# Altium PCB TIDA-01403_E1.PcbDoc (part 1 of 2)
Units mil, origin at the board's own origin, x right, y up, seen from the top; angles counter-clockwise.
Board outline 4150 x 3450 mil, 4 copper layers (Top Layer, GND, PWR, Bottom Layer), stack 61.6 mil thick; 155 components, 99 nets, 498 pads, 229 vias.
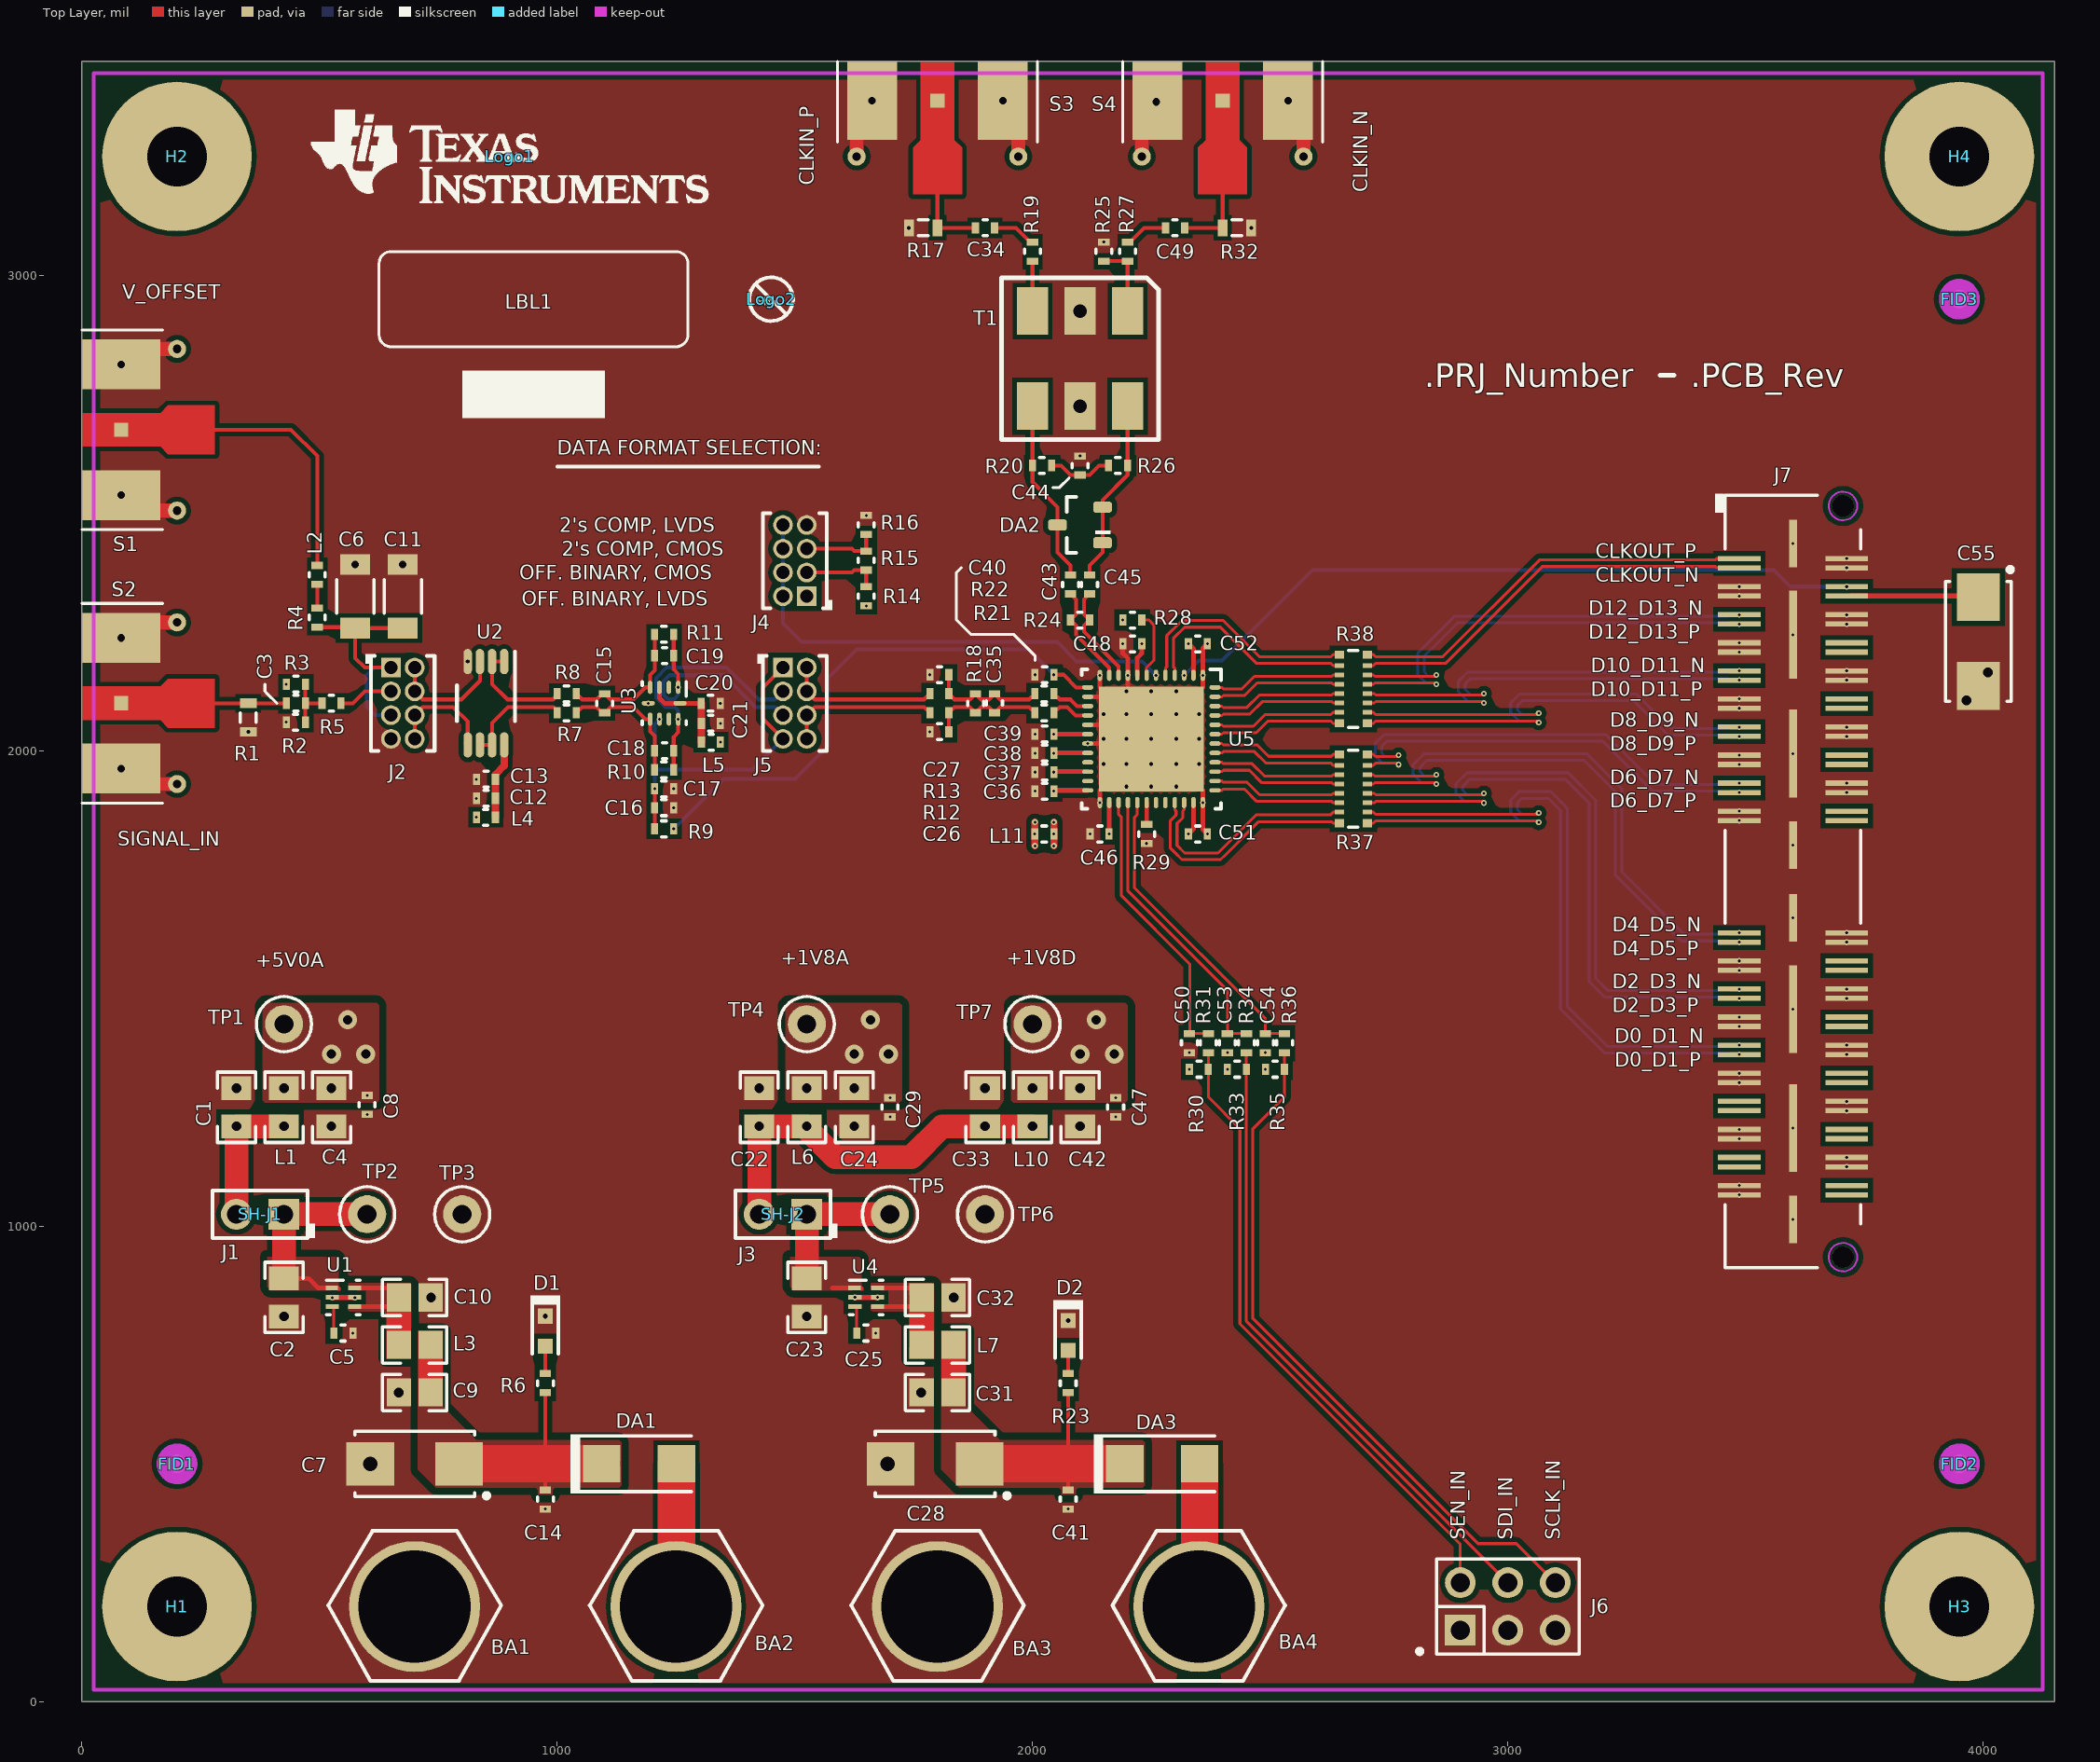
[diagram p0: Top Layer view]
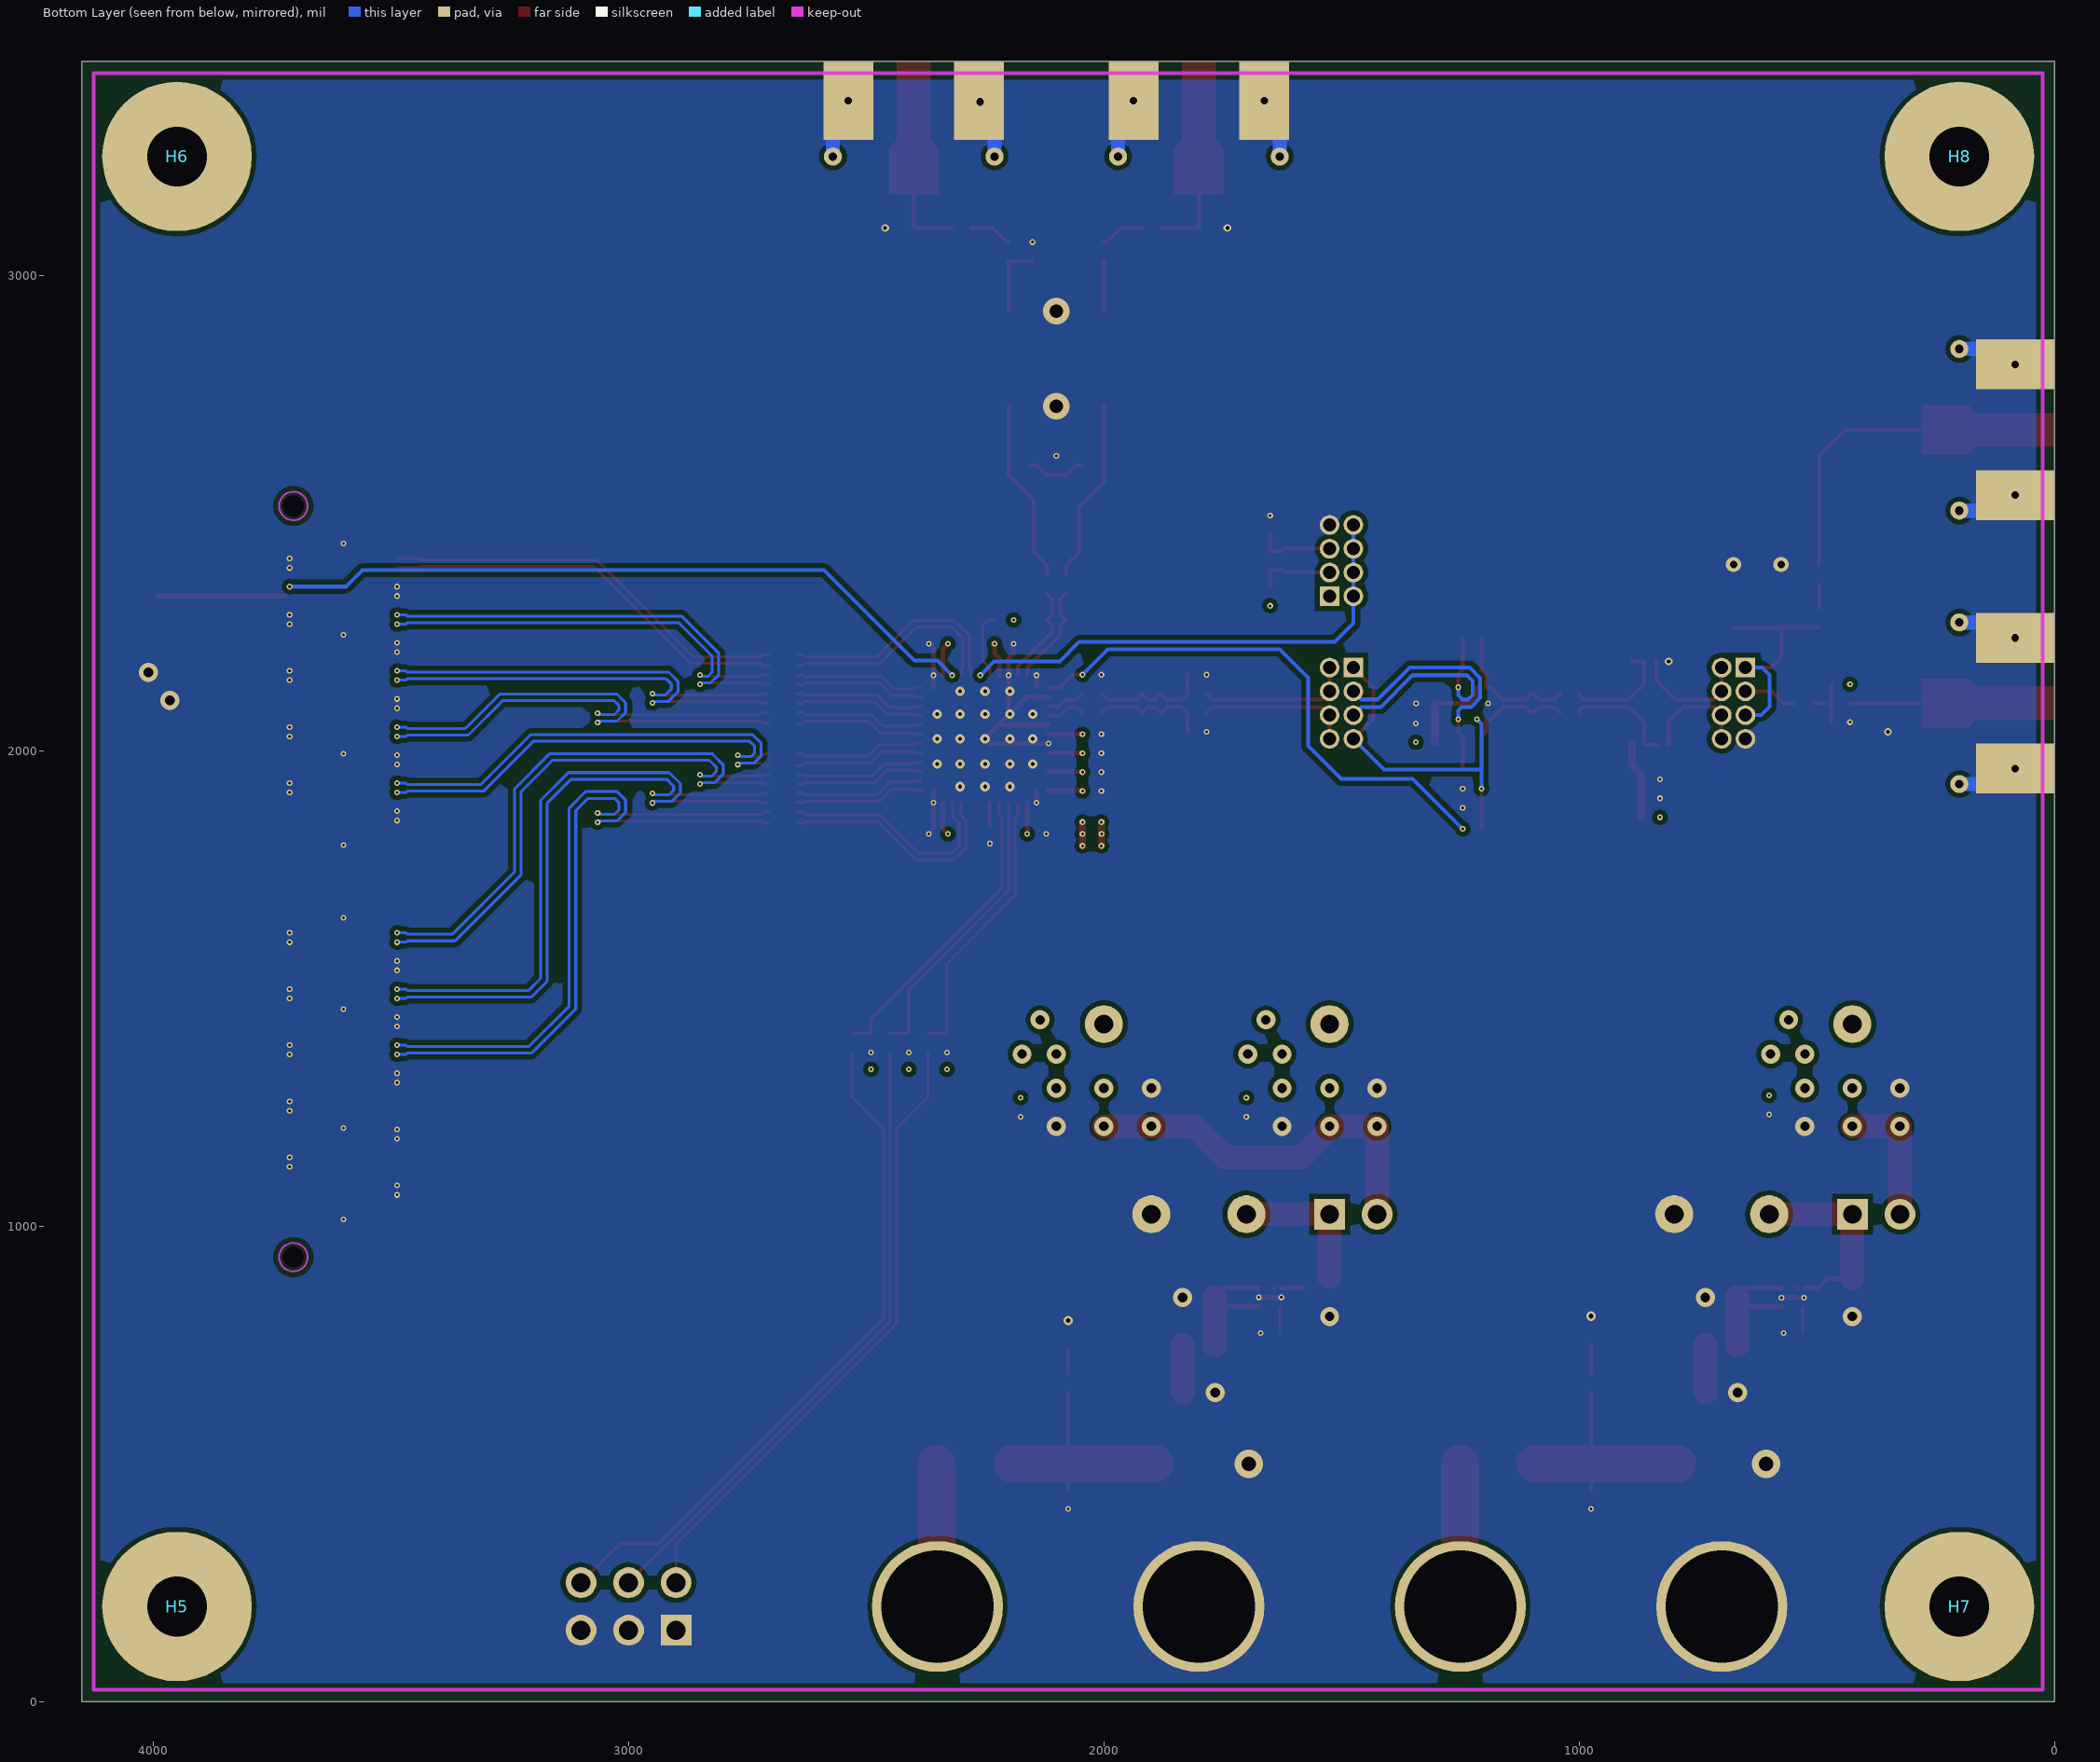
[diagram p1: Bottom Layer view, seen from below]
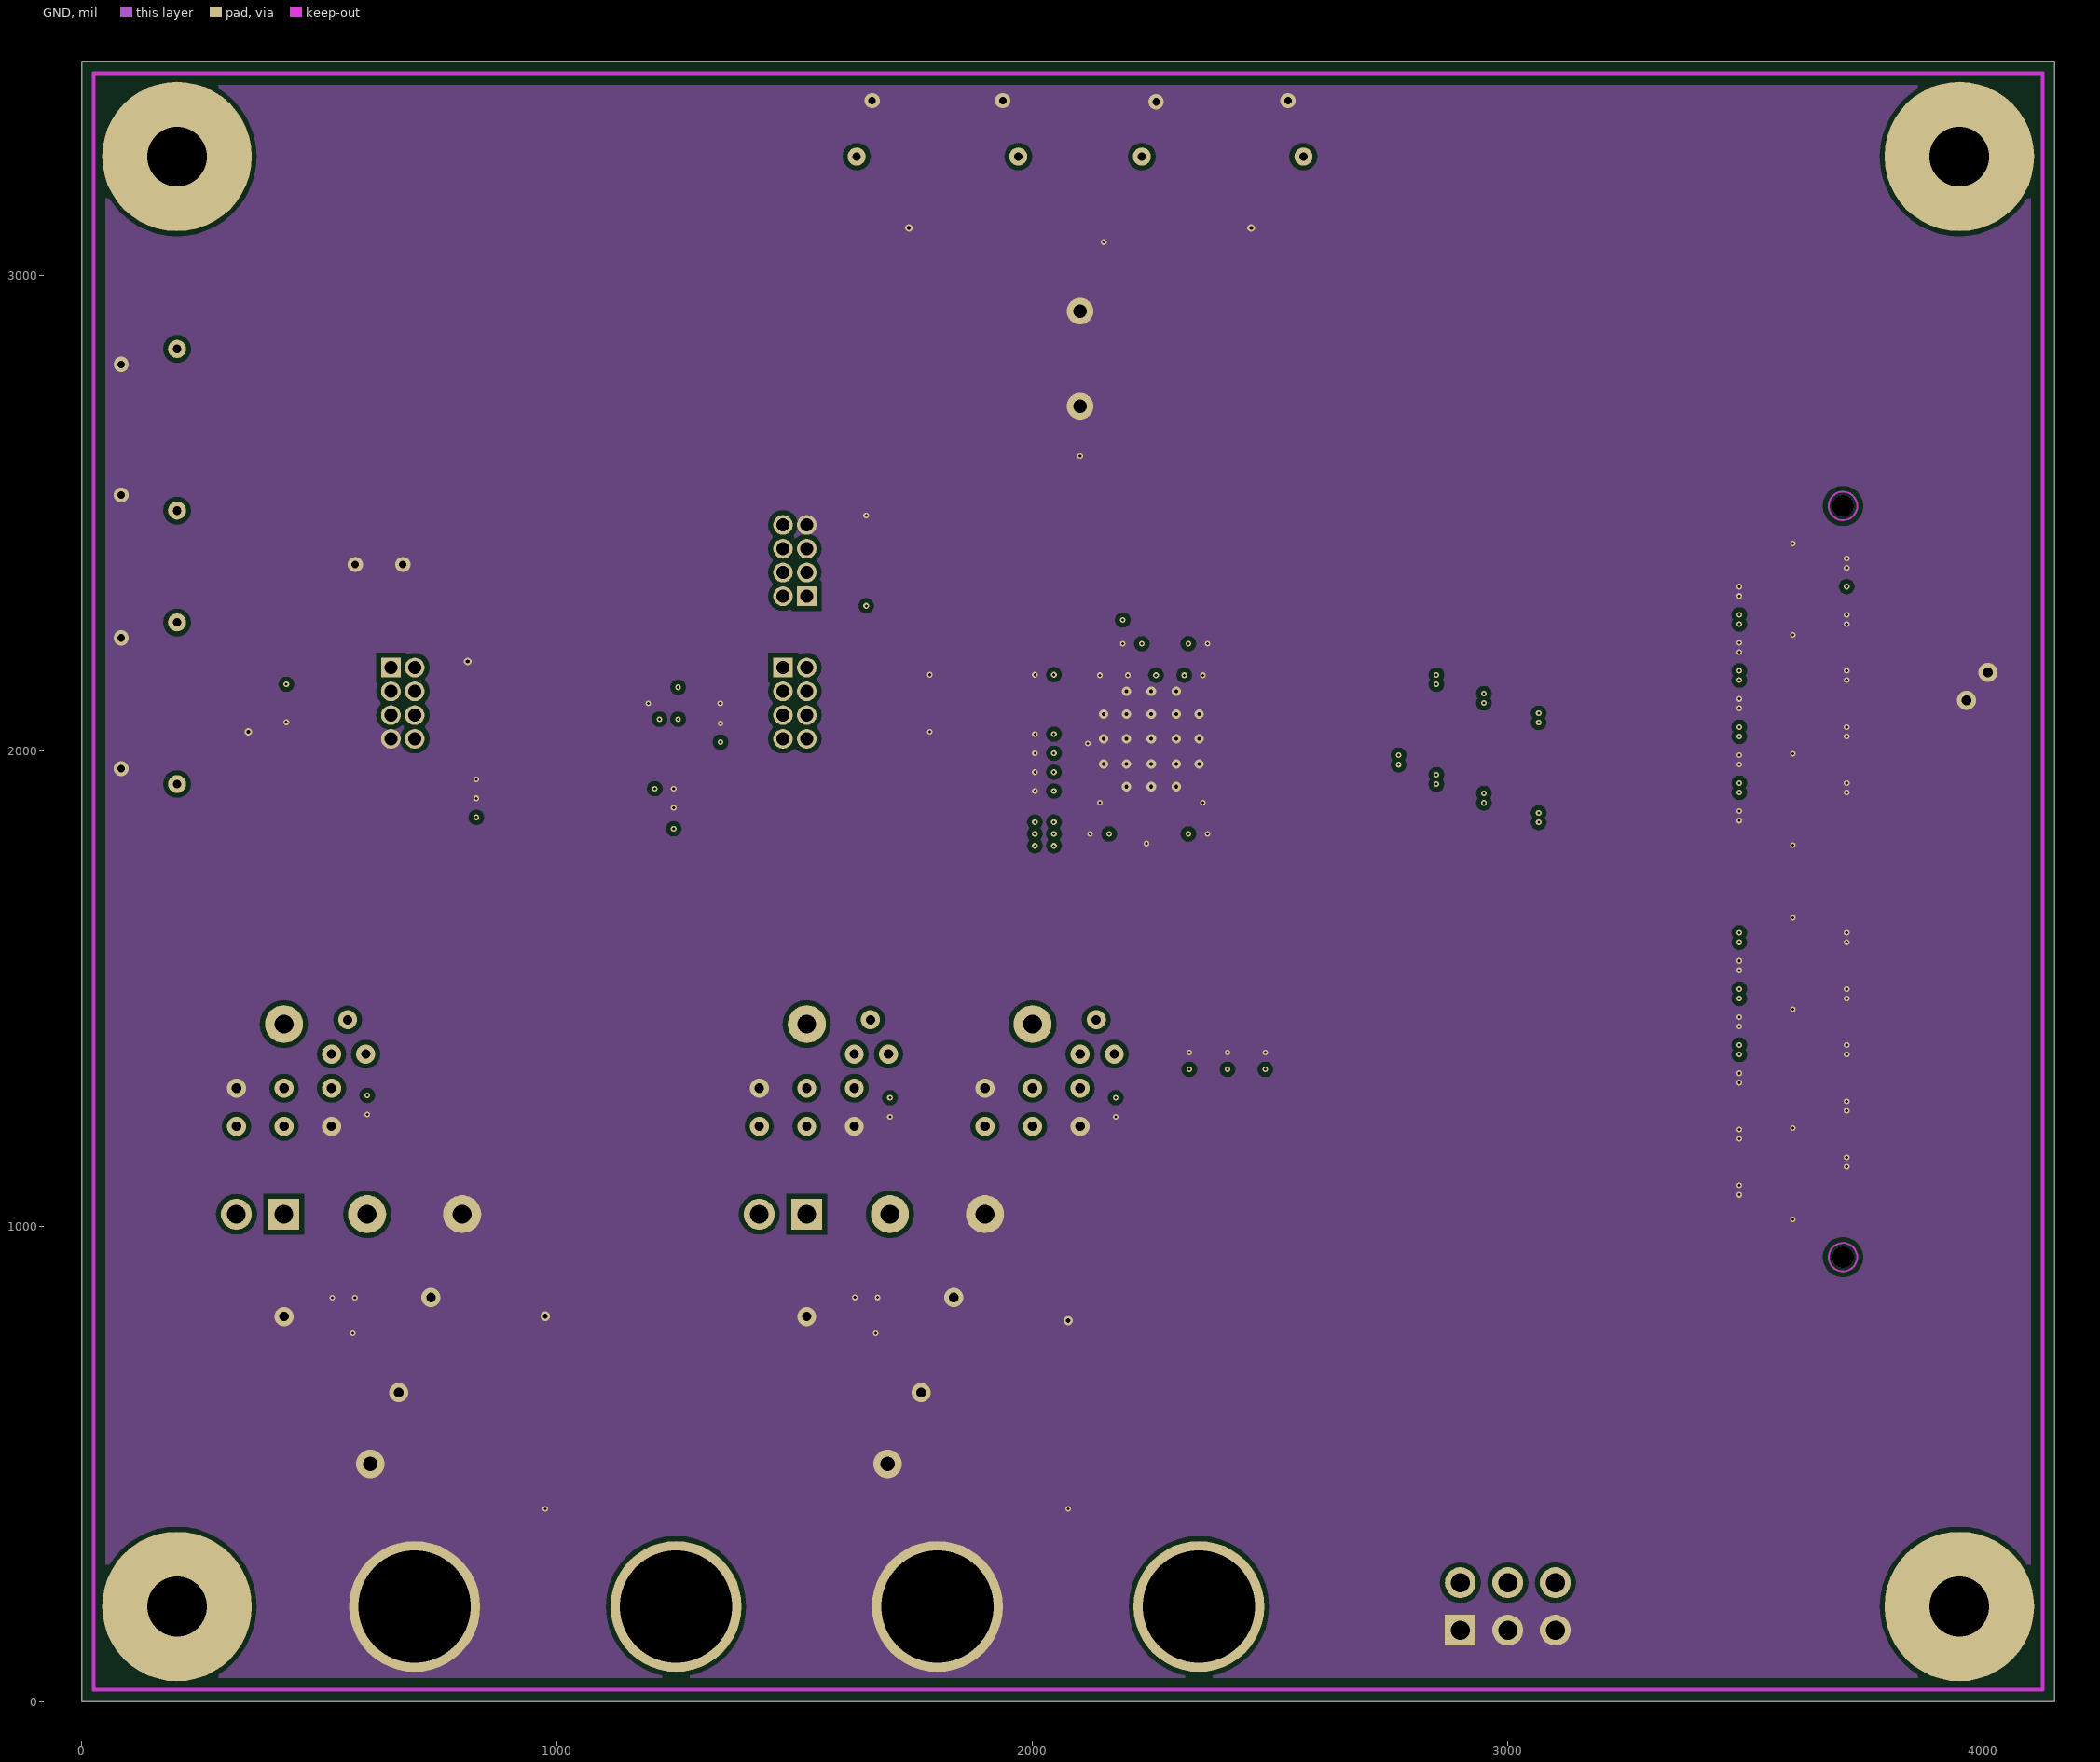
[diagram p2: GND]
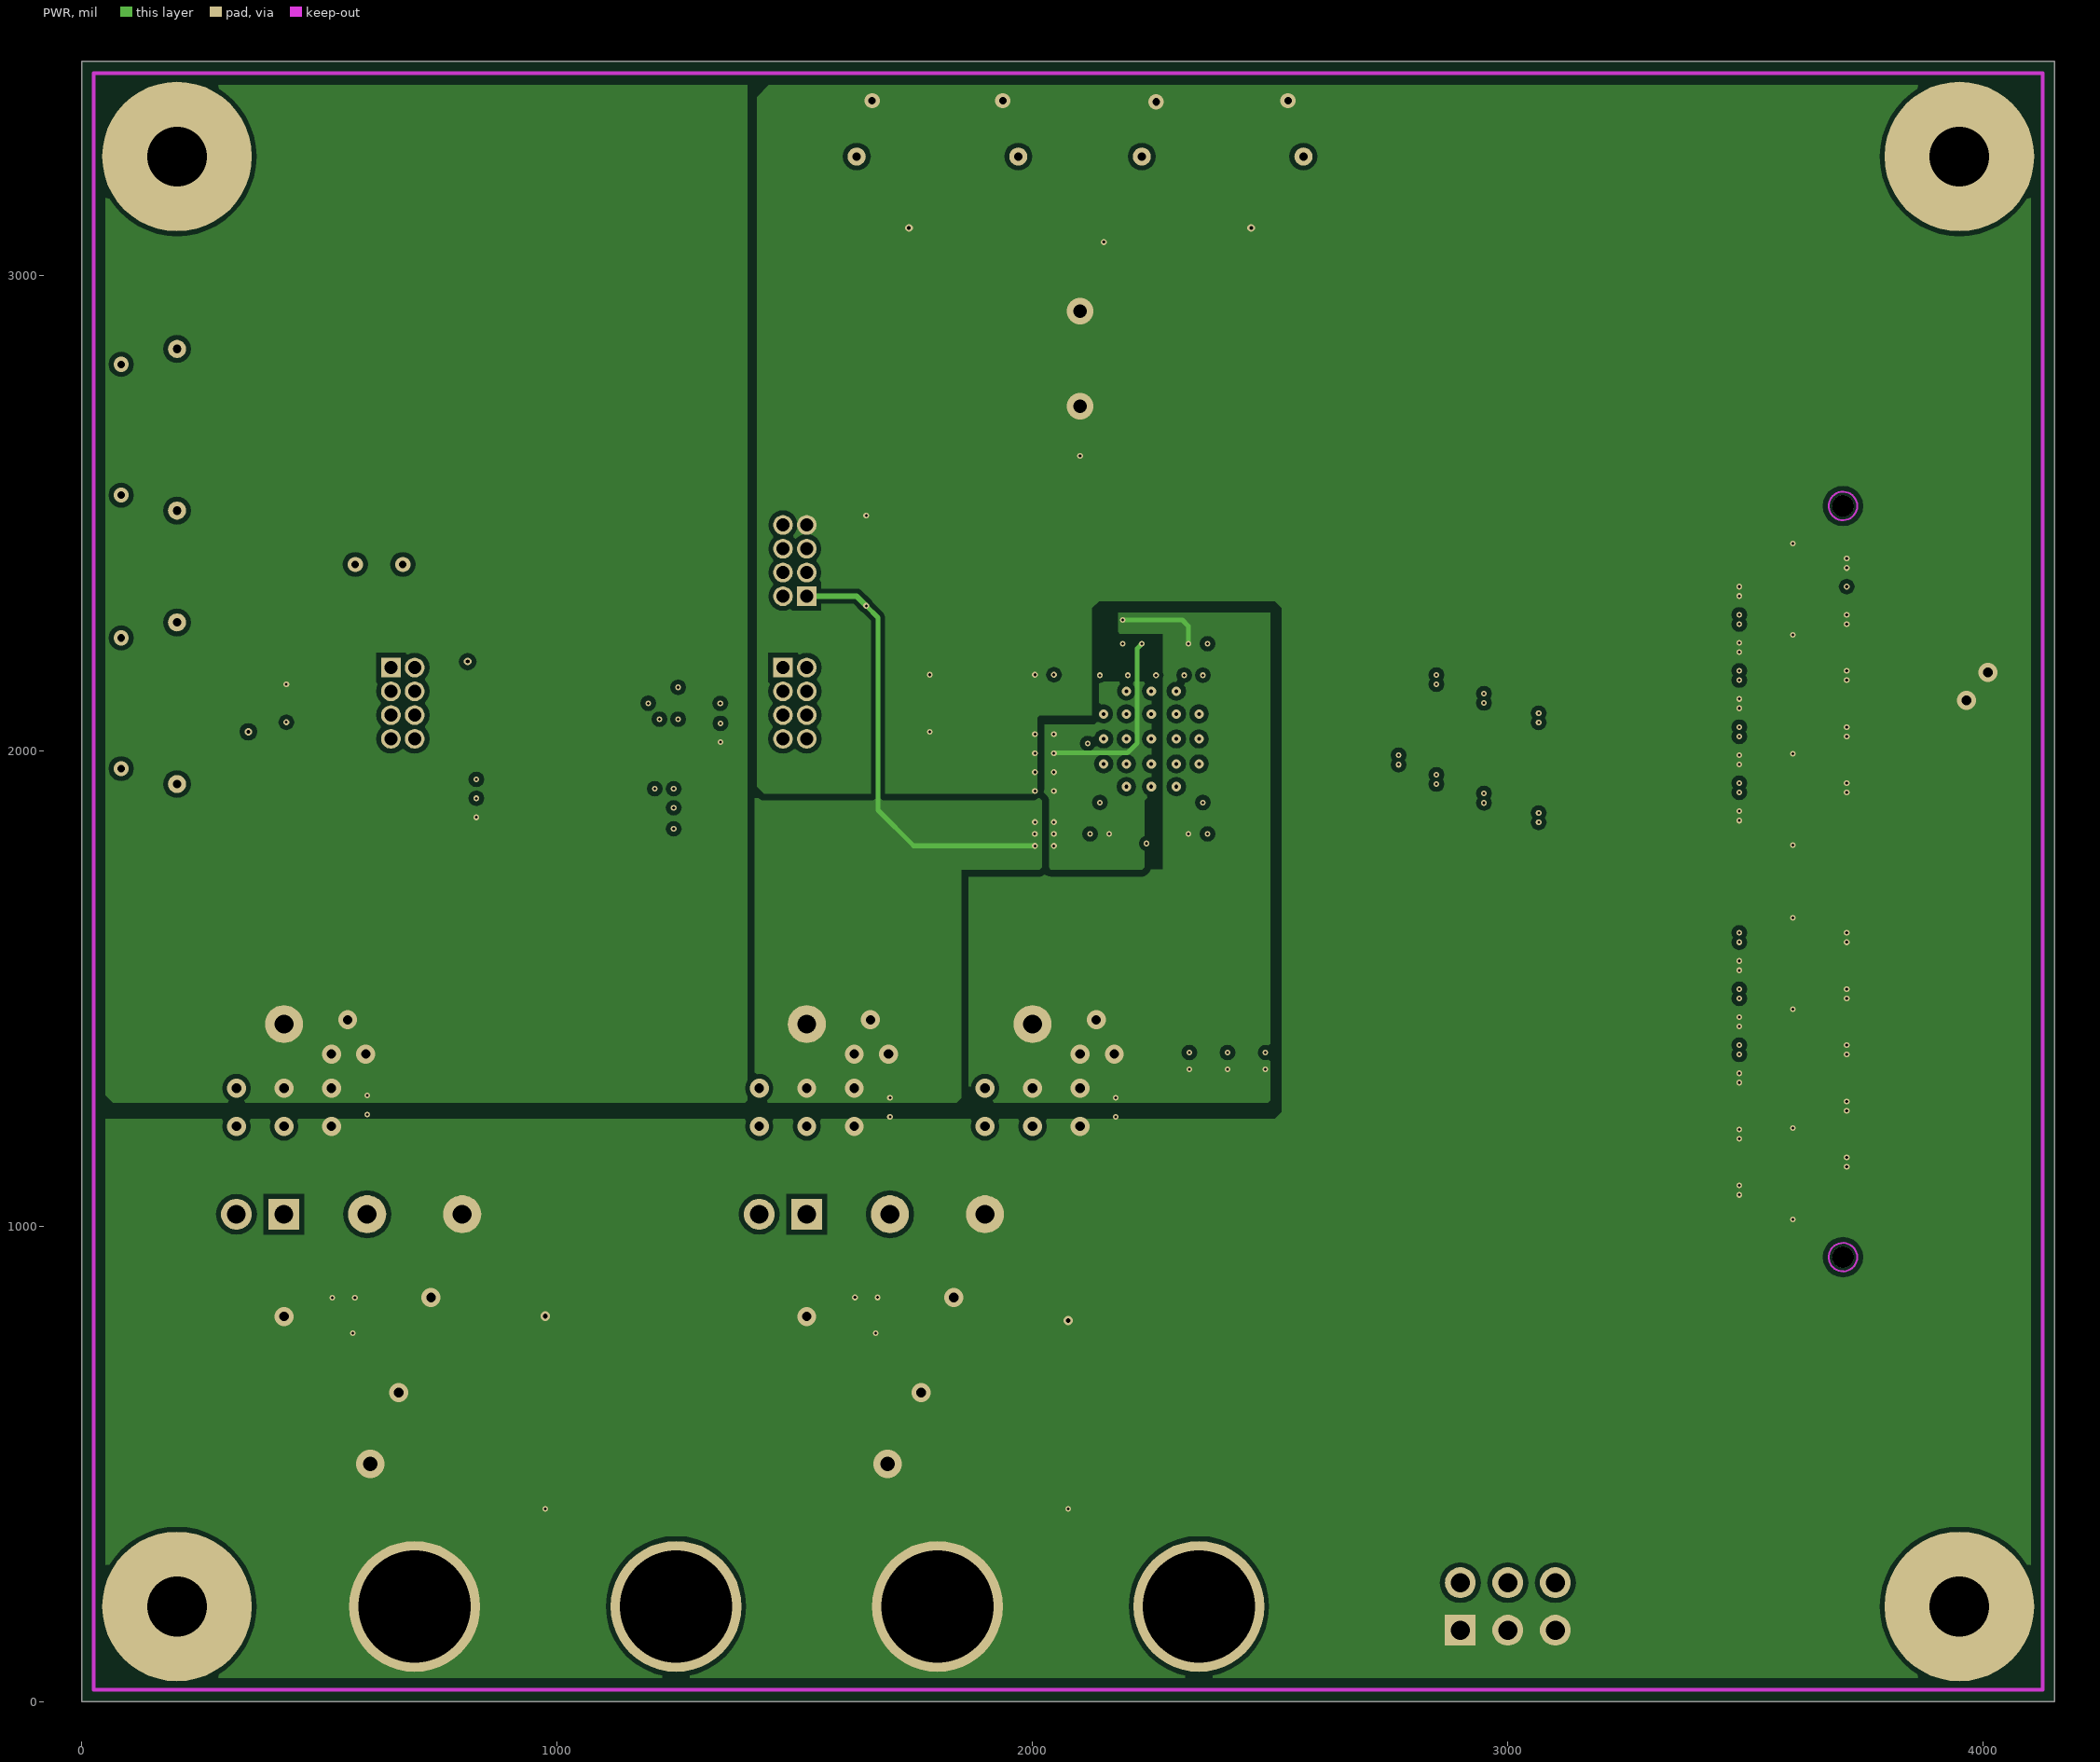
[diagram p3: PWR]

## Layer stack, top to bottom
Top Solder: solder mask 0.4, Solder Resist, Dk 3.5
Top Layer: signal copper 1.4
Dielectric 1: prepreg 8, FR-4 High Tg, Dk 4.2
GND: signal copper 1.4
Dielectric 2: core 40, FR-4 High Tg, Dk 4.2
PWR: signal copper 1.4
Dielectric 3: prepreg 8, FR-4 High Tg, Dk 4.2
Bottom Layer: signal copper 1.4
Bottom Solder: solder mask 0.4, Solder Resist, Dk 3.5

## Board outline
0,0 0,3450 4150,3450 4150,0

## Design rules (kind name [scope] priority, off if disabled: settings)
AcuteAngle [All] p1: minimum=4.50000000000000E+0001 checktracksonly=FALSE
AssemblyTestPointUsage [All] p1: valid=2
Clearance "Clearance_poly to poly" [InPolygon vs InPolygon] p1: gap=15 ignorepadtopadclearanceinfootprint=FALSE except(0: Arc-Hole Track-Hole SMDPad-Hole THPad-Hole Via-Hole Fill-Hole Poly-Hole Region-Hole Text-Hole)
Clearance Clearance_Keepouts [((IsTrack Or IsArc) And Not InPoly) And IsFree and IsKeepOut vs ((IsTrack Or IsArc) And Not InPoly) And IsFree and IsKeepOut] p2: gap=0 ignorepadtopadclearanceinfootprint=FALSE
Clearance Clearance_Poly [InPolygon] p3: gap=10 ignorepadtopadclearanceinfootprint=FALSE except(0: Arc-Hole Track-Hole SMDPad-Hole THPad-Hole Via-Hole Fill-Hole Poly-Hole Region-Hole Text-Hole)
Clearance [All] p4: gap=7.65 ignorepadtopadclearanceinfootprint=FALSE except(0: Arc-Hole Track-Hole SMDPad-Hole THPad-Hole Via-Hole Fill-Hole Poly-Hole Region-Hole Text-Hole)
ComponentClearance ComponentClearance_MountingHoles_FiducialMarks [InComponentClass('Mounting Holes') vs InComponentClass('FiducialMark')] p1: gap=50 collisioncheckmode=3 verticalgap=10 showdistances=FALSE
ComponentClearance ComponentClearance_Shunt [InComponentClass('Header') vs InComponentClass('Shunt')] p2: gap=0 collisioncheckmode=3 verticalgap=0 showdistances=FALSE
ComponentClearance ComponentClearance_Logo [InComponentClass('Logo')] p3: gap=0 collisioncheckmode=3 verticalgap=0 showdistances=FALSE
ComponentClearance ComponentClearance_ScrewToNut [(HasFootprint('NY PMS 440 0025 PH')) vs (HasFootprint('Keystone_1902C'))] p4: gap=5 collisioncheckmode=3 verticalgap=10 showdistances=FALSE
ComponentClearance ComponentClearance_MountingHoles [InComponentClass('Mounting Holes')] p5: gap=100 collisioncheckmode=3 verticalgap=100000 showdistances=FALSE
ComponentClearance ComponentClearance_SmallPassives [HasFootprint('0201*') or HasFootprint('0402*') or HasFootprint('0508') or HasFootprint('0603*') or HasFootprint('0612') or HasFootprint('0805*') or HasFootprint('0815*') or HasFootprint('0830*') or HasFootprint('1206*') or HasFootprint('1210*') or HasFootprint('1808*') or HasFootprint('1812*') or HasFootprint('1825*') or HasFootprint('2010*') or HasFootprint('2220*') or HasFootprint('2225*') or HasFootprint('2512*') or HasFootprint('2728*') or HasFootprint('3518*') vs HasFootprint('0201*') or HasFootprint('0402*') or HasFootprint('0508') or HasFootprint('0603*') or HasFootprint('0612') or HasFootprint('0805*') or HasFootprint('0815*') or HasFootprint('0830*') or HasFootprint('1206*') or HasFootprint('1210*') or HasFootprint('1808*') or HasFootprint('1812*') or HasFootprint('1825*') or HasFootprint('2010*') or HasFootprint('2220*') or HasFootprint('2225*') or HasFootprint('2512*') or HasFootprint('2728*') or HasFootprint('3518*')] p6: gap=0 collisioncheckmode=3 verticalgap=0 showdistances=FALSE
ComponentClearance ComponentClearance_THtoSMT [IsThruComponent vs IsSMTComponent] p7: gap=0 collisioncheckmode=3 verticalgap=0 showdistances=FALSE
ComponentClearance ComponentClearance_THtoTH [IsThruComponent vs IsThruComponent] p8: gap=30 collisioncheckmode=3 verticalgap=30 showdistances=FALSE
ComponentClearance [All] p9: gap=0 collisioncheckmode=3 verticalgap=0 showdistances=FALSE
DiffPairsRouting [All] p1: maxlimit=100 minlimit=6 mostfreqgap=10 toplayer_maxgap=10 toplayer_prefgap=8 toplayer_minwidth=6 toplayer_maxwidth=15 toplayer_prefwidth=8 midlayer1_mingap=10 midlayer1_minwidth=15 midlayer1_maxwidth=15 midlayer1_prefwidth=15 midlayer2_mingap=10 midlayer2_minwidth=15 midlayer2_maxwidth=15 midlayer2_prefwidth=15 bottomlayer_maxgap=10 bottomlayer_prefgap=8 bottomlayer_minwidth=6 bottomlayer_maxwidth=15 bottomlayer_prefwidth=8 maxuncoupledlength=1000
FabricationTestPointUsage TestPointUsage [All] p1: valid=2 allowmultiple=FALSE
FabricationTestpoint Testpoint [All] p1: side=3 testpointundercomponent=TRUE minsize=40 maxsize=100 preferedsize=60 minholesize=0 maxholesize=40 preferedholesize=32 testpointgrid=1 allowsidetop=TRUE allowsidebottom=TRUE usegrid=TRUE gridtolerance=0.01
FanoutControl Fanout_LCC [IsLCC] p1: bgadir=Out bgaviamode=Centered fanoutstyle=Auto fanoutdirection=Alternating viagrid=1 // Fanout_LCC (Default Rule)
FanoutControl Fanout_BGA [IsBGA] p2: bgadir=Out bgaviamode=Centered fanoutstyle=Auto fanoutdirection=Alternating viagrid=1 // Fanout_BGA (Default Rule)
FanoutControl Fanout_Default [All] p4: bgadir=Out bgaviamode=Centered fanoutstyle=Auto fanoutdirection=Alternating viagrid=1 // Fanout_Default (Default Rule)
FanoutControl Fanout_Small [(CompPinCount < 5)] p5: bgadir=Out bgaviamode=Centered fanoutstyle=Auto fanoutdirection=OutThenIn viagrid=1 // Fanout_Small (Default Rule)
HoleSize [All] p1: absolutevalues=TRUE maxlimit=251 minlimit=4 maxpercent=80.000 minpercent=20.000
MinimumAnnularRing [All] p1: minimumring=6
MinimumSolderMaskSliver MinimumSolderMaskSliver_Logo [InComponentClass('Logo') vs InComponentClass('Logo')] p1: minsoldermaskwidth=0.7
MinimumSolderMaskSliver [All] p2: minsoldermaskwidth=3.94
PlaneConnect [All] p1: planeconnectstyle=Direct reliefexpansion=10 reliefentries=4 reliefconductorwidth=10 reliefairgap=10
PolygonConnect [All] p1: connectstyle=Direct reliefconductorwidth=10 reliefentries=4 polygonreliefangle="90 Angle" airgapwidth=10
RoutingVias ThermalPadVias [IsVia and InAnyComponent] p1: holewidth=7.87 width=19.68 viastyle="Through Hole" minholewidth=7.87 minwidth=19.68 maxholewidth=12.99 maxwidth=23.62
RoutingVias [All] p2: holewidth=6 width=12 viastyle="Through Hole" minholewidth=6 minwidth=12 maxholewidth=30 maxwidth=60
SilkToBoardRegionClearance [Not ((IsComment or IsDesignator) And (Hide <> 'False')) and not InRegion(1000,500,4000,800)] p1:
SilkToSilkClearance SilkToSilkClearance_Pb-FreeLogo [(HasFootprint('Pb-Free_Overlay_Medium') OR HasFootprint('Pb-Free_Overlay_Small')) vs (HasFootprint('Pb-Free_Overlay_Medium') OR HasFootprint('Pb-Free_Overlay_Small'))] p1: silktosilkclearance=0
SilkToSilkClearance [All] p2: silktosilkclearance=4
SilkToSolderMaskClearance SilkToComponentPadClearance [(IsPad or IsFill or IsRegion) and InAnycomponent] p1: minsilkscreentomaskgap=5 clearancetoexposedcopper=TRUE
SilkToSolderMaskClearance "Silk to Solder Mask Opening" [All] p2: minsilkscreentomaskgap=4 clearancetoexposedcopper=FALSE
SolderMaskExpansion [All] p1: expansion=2
Width [All] p1: maxlimit=100 minlimit=6 preferedwidth=20 checkconnectedcopper=TRUE
15 further rules are at their usual default settings.

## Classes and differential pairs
pad class hole: H1-1 H2-1 H3-1 H4-1
component class Shunt: SH-J1 SH-J2
component class Label: LBL1
component class AssemblyNote: ZZ1 ZZ2 ZZ3 ZZ4
component class FiducialMark: FID1 FID2 FID3
component class TIDA-01403_E1_EVM_Hardware: FID1 FID2 FID3 H1 H2 H3 H4 H5 H6 H7 H8 LBL1 Logo1 Logo2 Logo3 ZZ1 ZZ2 ZZ3 ZZ4
component class Logo: Logo1
component class "Mounting Holes": H1 H2 H3 H4
component class Header: J1 J2 J3 J4 J5 J6
component class TIDA-01403_E1_SchSheet_2: C3 C6 C11 C12 C13 C15 C16 C17 C18 C19 C20 C21 C26 C27 C34 C35 C36 C37 C38 C39 C40 C43 C44 C45 C46 C48 C49 C51 C52 DA2 J2 J4 J5 L2 L4 L5 L11 R1 R2 R3 R4 R5 R7 R8 R9 R10 R11 R12 R13 R14 R15 R16 R17 R18 R19 R20 R21 R22 R24 R25 R26 R27 R28 R29 R32 S1 S2 S3 S4 SH-J1 SH-J2 SH-J3 SH-J4 SH-J5 T1 U2 U3 U5
component class TIDA-01403_E1_SchSheet_3: BA1 BA2 BA3 BA4 C1 C2 C4 C5 C7 C8 C9 C10 C14 C22 C23 C24 C25 C28 C29 C31 C32 C33 C41 C42 C47 C50 C53 C54 C55 D1 D2 DA1 DA3 J1 J3 J6 J7 L1 L3 L6 L7 L10 R6 R23 R30 R31 R33 R34 R35 R36 R37 R38 SH-J1 SH-J2 TP1 TP2 TP3 TP4 TP5 TP6 TP7 U1 U4
differential pair ACLKOUT: +ACLKOUT_P -ACLKOUT_N
differential pair AD0_AD1: +AD0_AD1_P -AD0_AD1_N
differential pair AD2_AD3: +AD2_AD3_P -AD2_AD3_N
differential pair AD4_AD5: +AD4_AD5_P -AD4_AD5_N
differential pair AD6_AD7: +AD6_AD7_P -AD6_AD7_N
differential pair AD8_AD9: +AD8_AD9_P -AD8_AD9_N
differential pair AD10_AD11: +AD10_AD11_P -AD10_AD11_N
differential pair AD12_AD13: +AD12_AD13_P -AD12_AD13_N
differential pair ADCIN: +ADCIN_P -ADCIN_N
differential pair CLKOUT: +CLKOUT_P -CLKOUT_N
differential pair CLK: +CLK_P -CLK_N
differential pair D0_D1: +D0_D1_P -D0_D1_N
differential pair D2_D3: +D2_D3_P -D2_D3_N
differential pair D4_D5: +D4_D5_P -D4_D5_N
differential pair D6_D7: +D6_D7_P -D6_D7_N
differential pair D8_D9: +D8_D9_P -D8_D9_N
differential pair D10_D11: +D10_D11_P -D10_D11_N
differential pair D12_D13: +D12_D13_P -D12_D13_N
differential pair FDA_VIN: +FDA_VIN_P -FDA_VIN_N
differential pair FDAOUT: +FDAOUT_P -FDAOUT_N
differential pair FILIN: +FILIN_P -FILIN_N
differential pair FIL: +FILOUT_P -FILOUT_N
differential pair OPAIN: +OPAIN_P -OPAIN_N
differential pair OPAOUT: +OPAOUT_P -OPAOUT_N

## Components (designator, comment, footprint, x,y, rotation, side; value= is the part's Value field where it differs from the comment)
BA1 "CT2220" BKP_CT2220 700,200 r0 top
BA2 "CT2220" BKP_CT2220 1250,200 r0 top
BA3 "CT2220" BKP_CT2220 1800,200 r0 top
BA4 "CT2220" BKP_CT2220 2350,200 r0 top
C1 "GRM21BZ71E106KE15L" 0805_HV 325,1250 r90 top value=10uF
C2 "GRM21BZ71E106KE15L" 0805_HV 425,850 r270 top value=10uF
C3 "GRM155R71C104KA88D" 0402S 450,2100 r180 top value=0.1uF
C4 "GRM21BZ71E106KE15L" 0805_HV 525,1250 r270 top value=10uF
C5 "GRM155R71E104KE14D" 0402S 550,775 r0 top value=0.1uF
C6 "LMK316AB7226KL-TR" 1206_180 575,2325 r270 top value=22uF
C7 "593D106X9016C2TE3" 6032-28 700,500 r180 top value=10uF
C8 "GRM155R71C104KA88D" 0402S 600,1255 r270 top value=0.1uF
C9 "GRM21BZ71E106KE15L" 0805 700,650 r180 top value=10uF
C10 "GRM21BZ71E106KE15L" 0805 700,850 r0 top value=10uF
C11 "LMK316AB7226KL-TR" 1206_180 675,2325 r270 top value=22uF
C12 "GRM155R61C475ME15" 0402S 850,1900 r180 top value=4.7uF
C13 "GRM155R71C104KA88D" 0402S 850,1940 r180 top value=0.1uF
C14 "GRM155R71C104KA88D" 0402S 975,425 r270 top value=0.1uF
C15 "GRM1555C1H130JA01D" 0402S 1100,2100 r90 top value=13pF
C16 "GRM155R61E105KA12D" 0402S 1225,1880 r0 top value=1uF
C17 "GRM155R71E104KE14D" 0402S 1225,1920 r0 top value=0.1uF
C18 "GRM1555C1E4R7CA01D" 0402S 1225,2000 r180 top value=4.7pF
C19 "GRM1555C1E4R7CA01D" 0402S 1225,2200 r180 top value=4.7pF
C20 "GRM155R71C104KA88D" 0402S 1323,2099.79 r0 top value=0.1uF
C21 "GRM155R61C475ME15" 0402S 1323.16,2057.73 r0 top value=4.7uF
C22 "GRM21BZ71E106KE15L" 0805_HV 1425,1250 r90 top value=10uF
C23 "GRM21BZ71E106KE15L" 0805_HV 1525,850 r270 top value=10uF
C24 "GRM21BZ71E106KE15L" 0805_HV 1625,1250 r270 top value=10uF
C25 "GRM155R71E104KE14D" 0402S 1650,775 r0 top value=0.1uF
C26 "885012005043" 0402S 1804,2040 r180 top value=33pF
C27 "885012005043" 0402S 1804,2160 r180 top value=33pF
C28 "593D106X9016C2TE3" 6032-28 1795,500 r180 top value=10uF
C29 "GRM155R71C104KA88D" 0402S 1700,1250 r270 top value=0.1uF
C31 "GRM21BZ71E106KE15L" 0805 1800,650 r180 top value=10uF
C32 "GRM21BZ71E106KE15L" 0805 1800,850 r0 top value=10uF
C33 "GRM21BZ71E106KE15L" 0805_HV 1900,1250 r90 top value=10uF
C34 "GRM155R71C104KA88D" 0402S 1900,3100 r180 top value=0.1uF
C35 "GRM1555C1H560JA01D" 0402S 1920,2100 r270 top value=56pF
C36 "GRM155R71C104KA88D" 0402S 2025,1915 r180 top value=0.1uF
C37 "GRM155R71C104KA88D" 0402S 2025,1955 r180 top value=0.1uF
C38 "GRM155R71C104KA88D" 0402S 2025,1995 r180 top value=0.1uF
C39 "GRM155R71C104KA88D" 0402S 2025,2035 r180 top value=0.1uF
C40 "GRM155R71E104KE14D" 0402S 2025,2160 r180 top value=0.1uF
C41 "GRM155R71C104KA88D" 0402S 2075,425 r270 top value=0.1uF
C42 "GRM21BZ71E106KE15L" 0805_HV 2100,1250 r270 top value=10uF
C43 "GRM155R71C104KA88D" 0402S 2080,2350 r90 top value=0.1uF
C44 "GRM155R71C104KA88D" 0402S 2100,2600 r90 top value=0.1uF
C45 "GRM155R71C104KA88D" 0402S 2120,2350 r90 top value=0.1uF
C46 "GRM155R71C104KA88D" 0402S 2141,1825 r180 top value=0.1uF
C47 "GRM155R71C104KA88D" 0402S 2175,1250 r270 top value=0.1uF
C48 "GRM155R71C104KA88D" 0402S 2210,2225 r180 top value=0.1uF
C49 "GRM155R71C104KA88D" 0402S 2300,3100 r0 top value=0.1uF
C50 "CC0402KRX7R9BB101" 0402S 2330,1385 r270 top value=100pF
C51 "GRM155R71C104KA88D" 0402S 2348,1825 r0 top value=0.1uF
C52 "GRM155R71C104KA88D" 0402S 2348,2225 r0 top value=0.1uF
C53 "CC0402KRX7R9BB101" 0402S 2410,1385 r270 top value=100pF
C54 "CC0402KRX7R9BB101" 0402S 2490,1385 r270 top value=100pF
C55 "593D106X9016C2TE3" 6032-28 3990,2230 r270 top value=10uF
D1 "150060RS75000" WL-SMCW_RED 975,779.24 r270 top value=Red
D2 "150060RS75000" WL-SMCW_RED 2075,770 r270 top value=Red
DA1 "SS14HE3_A/H" SMA 1172,500 r0 top value=40V
DA2 "DB3X316F0L" SOT-23 2100,2475 r180 top value=30V
DA3 "SS14HE3_A/H" SMA 2273,500 r0 top value=40V
FID1 "Fiducial" Fiducial10-20 200,500 r0 top
FID2 "Fiducial" Fiducial10-20 3950,500 r0 top
FID3 "Fiducial" Fiducial10-20 3950,2950 r0 top
H1 "NY PMS 440 0025 PH" "NY PMS 440 0025 PH" 200,200 r0 top locked
H2 "NY PMS 440 0025 PH" "NY PMS 440 0025 PH" 200,3250 r0 top locked
H3 "NY PMS 440 0025 PH" "NY PMS 440 0025 PH" 3950,200 r0 top locked
H4 "NY PMS 440 0025 PH" "NY PMS 440 0025 PH" 3950,3250 r0 top locked
H5 "1902C" Keystone_1902C 3950,200 r180 bottom locked
H6 "1902C" Keystone_1902C 3950,3250 r180 bottom locked
H7 "1902C" Keystone_1902C 200,200 r180 bottom locked
H8 "1902C" Keystone_1902C 200,3250 r180 bottom locked
J1 "5-146278-2" TE_5-146278-2 375,1025 r180 top
J2 "GRPB042VWVN-RC" Sullins_GRPB042VWVN 675,2100 r0 top
J3 "5-146278-2" TE_5-146278-2 1475,1025 r180 top
J4 "GRPB042VWVN-RC" Sullins_GRPB042VWVN 1500,2400 r180 top
J5 "GRPB042VWVN-RC" Sullins_GRPB042VWVN 1500,2100 r0 top
J6 "TSW-103-07-G-D" TSW-103-07-G-D 3000,200 r0 top
J7 "QSH-040-01-F-D-DP-A" SAMTEC_QSH-040-01-F-D-DP-A 3600,1735 r270 top locked
L1 "742792097" 0805_HV 425,1250 r90 top value="1500 ohm"
L2 "MMZ1005B601CTD25" 0402S 495,2370 r270 top value="600 ohm"
L3 "742792097" 0805 700,750 r180 top value="1500 ohm"
L4 "MMZ1005B601CTD25" 0402S 850,1860 r0 top value="600 ohm"
L5 "MMZ1005B601CTD25" 0402S 1323.24,2018 r180 top value="600 ohm"
L6 "742792097" 0805_HV 1525,1250 r90 top value="1500 ohm"
L7 "742792097" 0805 1800,750 r180 top value="1500 ohm"
L10 "742792097" 0805_HV 2000,1250 r90 top value="1500 ohm"
L11 "MMZ1005B601CTD25" 0402S 2025,1825 r0 top value="600 ohm"
LBL1 "Size: 0.65\" x 0.20 \"" Label_650x200 950,2950 r0 top
Logo1 "Texas Instruments" TI_Stacked_Overlay_Small 900,3250 r0 top
Logo2 "Pb-Free Symbol" Pb-Free_Overlay_Small 1450,2950 r0 top
Logo3 "FCC disclaimer" FCC_disclaimer 2036,4061 r0 top
R1 "CRCW060350R0FKEA" 0603S 350,2070 r90 top value=50
R2 "CRCW04022K49FKED" 0402S 450,2060 r0 top value=2.49k
R3 "CRCW04022K49FKED" 0402S 450,2140 r180 top value=2.49k
R4 "CRCW040210R0FKED" 0402S 495,2280 r270 top value=10.0
R5 "ERJ-2GE0R00X" 0402S 525,2100 r0 top value=0
R6 "CRCW04021K00JNED" 0402S 975,670 r90 top value=1.0k
R7 "ERA-2AEB102X" 0402S 1020,2080 r0 top value=1.00k
R8 "ERA-2AEB102X" 0402S 1020,2120 r0 top value=1.00k
R9 "CRCW040210R0FKED" 0402S 1225,1835.81 r0 top value=10.0
R10 "ERA-2AEB102X" 0402S 1225,1960 r0 top value=1.00k
R11 "ERA-2AEB102X" 0402S 1225,2245 r0 top value=1.00k
R12 "CRCW0402130RFKED" 0402S 1804,2080 r0 top value=130
R13 "CRCW0402130RFKED" 0402S 1804,2120 r0 top value=130
R14 "CRCW04023K00JNED" 0402S 1650,2325 r270 top value=3.0k
R15 "CRCW04022K00JNED" 0402S 1650,2400 r270 top value=2.0k
R16 "CRCW04023K00JNED" 0402S 1650,2475 r270 top value=3.0k
R17 "CRCW060350R0FKEA" 0603S 1770,3100 r0 top value=50
R18 "MCR01MRTF1002" 0402S 1880,2100 r90 top value=10.0k
R19 "ERJ-2GE0R00X" 0402S 2000,3050 r270 top value=0
R20 "CRCW0402100RFKED" 0402S 2020,2600 r0 top value=100
R21 "ERJ-2GE0R00X" 0402S 2025,2080 r0 top value=0
R22 "ERJ-2GE0R00X" 0402S 2025,2120 r0 top value=0
R23 "CRCW04021K00JNED" 0402S 2075,670 r90 top value=1.0k
R24 "CRCW0402100RFKED" 0402S 2100,2275 r0 top value=100
R25 "ERJ-2GE0R00X" 0402S 2150,3050 r270 top value=0
R26 "CRCW0402100RFKED" 0402S 2180,2600 r0 top value=100
R27 "ERJ-2GE0R00X" 0402S 2200,3050 r270 top value=0
R28 "CRCW040210K0JNED" 0402S 2210,2275 r180 top value=10k
R29 "CRCW040210K0JNED" 0402S 2240,1825 r90 top value=10k
R30 "CRCW040210K0FKED" 0402S 2350,1330 r180 top value=10.0k
R31 "CRCW04021K00FKED" 0402S 2370,1385 r270 top value=1.00k
R32 "CRCW060350R0FKEA" 0603S 2430,3100 r180 top value=50
R33 "CRCW040210K0FKED" 0402S 2430,1330 r180 top value=10.0k
R34 "CRCW04021K00FKED" 0402S 2450,1385 r270 top value=1.00k
R35 "CRCW040210K0FKED" 0402S 2510,1330 r180 top value=10.0k
R36 "CRCW04021K00FKED" 0402S 2530,1385 r270 top value=1.00k
R37 "EXB-2HV220JV" RESCAXS_EXB-2HV 2675,1920 r270 top value=22
R38 "EXB-2HV220JV" RESCAXS_EXB-2HV 2675,2130 r270 top value=22
S1 "142-0711-821" JOHNSON_142-0711-821 0,2675.28 r90 top locked
S2 "142-0711-821" JOHNSON_142-0711-821 0,2100 r90 top locked
S3 "142-0711-821" JOHNSON_142-0711-821 1800,3450 r0 top locked
S4 "142-0711-821" JOHNSON_142-0711-821 2400,3450 r0 top locked
SH-J1 "969102-0000-DA" SNT-100-BK-G 375,1025 r180 top value=1x2
SH-J2 "969102-0000-DA" SNT-100-BK-G 1475,1025 r180 top value=1x2
T1 "ADT1-1WT+" MNC_CD542 2100,2825 r270 top
TP1 "5003" Keystone5003 425,1425 r0 top
TP2 "5003" Keystone5003 600,1025 r0 top
TP3 "5001" Keystone5001 800,1025 r0 top
TP4 "5003" Keystone5003 1525,1425 r0 top
TP5 "5003" Keystone5003 1700,1025 r0 top
TP6 "5001" Keystone5001 1900,1025 r0 top
TP7 "5003" Keystone5003 2000,1425 r0 top
U1 "TPS71750DSET" DSE0006A 550,850 r0 top
U2 "OPA2626IDGKR" DGK0008A_N 850,2100 r270 top
U3 "THS4551IRUNR" RUN0010A 1225,2100 r270 top
U4 "TPS71718DSET" DSE0006A 1650,850 r0 top
U5 "ADS4142IRGZR" RGZ0048D 2250,2025 r270 top locked
ZZ1 "This Assembly Note is for PCB labels only" AssemblyNoteLabel 162,4309 r0 top
ZZ2 "These assemblies must comply with workmanship standards IPC-A-610 Class 2, unless otherwise specified." AssemblyNote 165,4052 r0 top
ZZ3 "These assemblies must be clean and free from flux and all contaminants. Use of no clean flux is not acceptable." AssemblyNote 165,4140.56 r0 top
ZZ4 "These assemblies are ESD sensitive, ESD precautions shall be observed." AssemblyNote 165,4229.11 r0 top

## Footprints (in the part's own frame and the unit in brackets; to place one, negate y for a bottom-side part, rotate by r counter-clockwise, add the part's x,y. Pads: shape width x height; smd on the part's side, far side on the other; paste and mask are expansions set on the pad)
0402S [mil] "Based on C0402S footprint from PADS legacy"
  rect 15x24 smd: 1(-20,0) 2(20,0)
  silkscreen extent -5,-17 4,17, body extent -22,-12 22,12, height 24
0603S [mil]
  rect 20x35 smd: 1(-30,0) 2(30,0)
  silkscreen extent -10,-17 10,17, body extent -34,-19 34,19, height 39
0805 [mm] "0805 from SM-752 data"
  rect 1.3x1.5 smd: 1(-0.85,0) 2(0.85,0)
  silkscreen extent -1.72,-0.97 1.72,0.97, body extent -1.1,-0.72 1.1,0.72, height 1.45
0805_HV [mil] "0805 with 30mil clearance between pads"
  rect 50x63 smd: 1(-40,0) 2(40,0)
  silkscreen extent -74,-40 74,40, body extent -43,-29 43,29, height 57
1206_180 [mm] "1206_180"
  rect 1.1x1.6 smd: 1(-1.7,0) 2(1.7,0)
  silkscreen extent -0.9,-1 0.9,1, body extent -1.75,-0.95 1.75,0.95, height 1.8
6032-28 [mm] "Medium Density IPC based on Vishay Sprague 293D datasheet."
  rect 2.55x2.3 smd: 1(-2.375,0) 2(2.375,0)
  silkscreen extent -3.96,-1.75 3.2,1.82, body extent -3.15,-1.75 3.15,1.75, height 2.8
AssemblyNote [mil] "Assembly Note"
AssemblyNoteLabel [mil] "Assembly Note for PCB Labels"
BKP_CT2220 [mm] "Banana Jack Connector Standard Banana Threaded, External (Nut), TH"
  round 7 hole 6: 1(0,0)
  silkscreen extent -4.62,-3.97 4.62,4.03, body extent -4.62,-4 4.62,4, height 4
DGK0008A_N [mm] "TSOP, 8-Leads, Body 3x3mm, Pitch 0.65mm, IPC Medium Density"
  oval 1.35x0.45 smd: 1(-2.225,0.975) 2(-2.225,0.325) 3(-2.225,-0.325) 4(-2.225,-0.975) 5(2.225,-0.975) 6(2.225,-0.325) 7(2.225,0.325) 8(2.225,0.975)
  silkscreen extent -2.75,-1.55 0.95,1.55, body extent -2.45,-1.5 2.45,1.5, height 0.96
DSE0006A [mm] "TI recommended land pattern"
  rect 0.66x0.25 smd: 1(-0.62,0.5)
  rect 0.7x0.25 smd: 2(-0.6,0) 3(-0.6,-0.5) 4(0.6,-0.5) 5(0.6,0) 6(0.6,0.5)
  Top Layer region: -0.3,0.625 -0.25,0.625 -0.15,0.525 -0.15,0.375 -0.3,0.375
  silkscreen extent -0.9,-0.92 0.9,0.92, body extent -0.77,-0.77 0.77,0.77, height 0.8
FCC_disclaimer [mil]
Fiducial10-20 [mm]
  round 1 smd mask+0.5: 1(0,0)
  Top Layer keep-out circle w1.178: c0,0 r0.5
JOHNSON_142-0711-821 [mil]
  rect 30x30 smd: 1(0,-82.5)
  rect 105x165 smd: 2(-137.5,-82.5) 3(137.5,-82.5)
  rect 105x165 smd far side: 4(-137.5,-82.5) 5(137.5,-82.5)
  round 38 hole 18: ""(-170,-200) ""(170,-200)
  Top Layer region: -51.5,-279.35 -51.5,-181.5 -35,-165 -35,0 35,0 35,-165 51.5,-181.5 51.5,-279.35
  silkscreen extent -210,-170 210,0, body extent -125,-150 125,375, height 140
Keystone5001 [mil] "For Keystone 500x miniature loop terminals"
  round 80 hole 40: 1(0,0)
  silkscreen extent -58,-58 58,58, body extent -49,-49 49,49, height 182
Keystone5003 [mil] "For Keystone 500x miniature loop terminals"
  round 80 hole 40: 1(0,0)
  silkscreen extent -58,-58 58,58, body extent -49,-49 49,49, height 182
Keystone_1902C [mil] "Hex Standoff, 4-40 threaded, nylon"
  body extent -145,-126 146,126, height 501
Label_650x200 [mil] "Thermal Transfer Label"
  silkscreen extent -325,-100 325,100, body extent -325,-100 325,100, height 1
MNC_CD542 [mil] "Mini-Circuits recommended land pattern 98-CD.doc rev K 11/06/06"
  rect 100x65 smd: 1(-100,100) 2(-100,0) 3(-100,-100) 4(100,-100) 5(100,0) 6(100,100)
  silkscreen extent -170,-165 170,165, body extent -141,-157 141,157, height 112
"NY PMS 440 0025 PH" [mm] "4-40 nylon screw and mounting hole"
  round 8 hole 3.2: 1(0,0)
  body extent -3.3,-3.3 3.3,3.3, height 2.69
Pb-Free_Overlay_Small [mil]
  silkscreen extent -46,-46 46,46
RESCAXS_EXB-2HV [mm] "Panasonic Resistor Array"
  rect 0.425x0.5 smd mask+0.07: 1(-1.837,-0.75) 8(1.837,-0.75) 9(1.837,0.75) 16(-1.837,0.75)
  rect 0.25x0.5 smd mask+0.07: 2(-1.25,-0.75) 3(-0.75,-0.75) 4(-0.25,-0.75) 5(0.25,-0.75) 6(0.75,-0.75) 7(1.25,-0.75) 10(1.25,0.75) 11(0.75,0.75) 12(0.25,0.75) 13(-0.25,0.75) 14(-0.75,0.75) 15(-1.25,0.75)
  silkscreen extent -2.05,-0.25 2.05,0.25, body extent -1.95,-0.8 1.95,0.8, height 0.55
RGZ0048D [mm] "QFN, 48-Leads, Body 7x7mm, Pitch 0.5mm, Thermal Pad 5.6x5.6mm, TI Recommended"
  oval 0.6x0.24 smd: 1(-3.4,2.75) 2(-3.4,2.25) 3(-3.4,1.75) 4(-3.4,1.25) 5(-3.4,0.75) 6(-3.4,0.25) 7(-3.4,-0.25) 8(-3.4,-0.75) 9(-3.4,-1.25) 10(-3.4,-1.75) 11(-3.4,-2.25) 12(-3.4,-2.75) 25(3.4,-2.75) 26(3.4,-2.25) 27(3.4,-1.75) 28(3.4,-1.25) 29(3.4,-0.75) 30(3.4,-0.25) 31(3.4,0.25) 32(3.4,0.75) 33(3.4,1.25) 34(3.4,1.75) 35(3.4,2.25) 36(3.4,2.75)
  oval 0.24x0.6 smd: 13(-2.75,-3.4) 14(-2.25,-3.4) 15(-1.75,-3.4) 16(-1.25,-3.4) 17(-0.75,-3.4) 18(-0.25,-3.4) 19(0.25,-3.4) 20(0.75,-3.4) 21(1.25,-3.4) 22(1.75,-3.4) 23(2.25,-3.4) 24(2.75,-3.4) 37(2.75,3.4) 38(2.25,3.4) 39(1.75,3.4) 40(1.25,3.4) 41(0.75,3.4) 42(0.25,3.4) 43(-0.25,3.4) 44(-0.75,3.4) 45(-1.25,3.4) 46(-1.75,3.4) 47(-2.25,3.4) 48(-2.75,3.4)
  rect 5.6x5.6 smd paste-2.8: 49(0,0)
  silkscreen extent -3.72,-3.72 3.72,3.72, body extent -3.57,-3.58 3.58,3.57, height 1.01
RUN0010A [mm]
  oval 0.7x0.25 smd: 1(-0.85,0.75) 2(-0.85,0.25) 3(-0.85,-0.25) 4(-0.85,-0.75) 6(0.85,-0.75) 7(0.85,-0.25) 8(0.85,0.25) 9(0.85,0.75)
  oval 0.25x0.7 smd: 5(0,-0.85) 10(0,0.85)
  silkscreen extent -1.15,-1.17 1.15,1.17, body extent -1.05,-1.05 1.05,1.05, height 0.81
SAMTEC_QSH-040-01-F-D-DP-A [mm] "SMD, 40x2 Position"
  rect 0.28x2.27 smd: 1(-17,-2.87) 2(-17,2.87) 3(-16.5,-2.87) 4(-16.5,2.87) 5(-15.5,-2.87) 6(-15.5,2.87) 7(-15,-2.87) 8(-15,2.87) 9(-14,-2.87) 10(-14,2.87) 11(-13.5,-2.87) 12(-13.5,2.87) 13(-12.5,-2.87) 14(-12.5,2.87) 15(-12,-2.87) 16(-12,2.87) 17(-11,-2.87) 18(-11,2.87) 19(-10.5,-2.87) 20(-10.5,2.87) 21(-9.5,-2.87) 22(-9.5,2.87) 23(-9,-2.87) 24(-9,2.87) 25(-8,-2.87) 26(-8,2.87) 27(-7.5,-2.87) 28(-7.5,2.87) 29(-6.5,-2.87) 30(-6.5,2.87) 31(-6,-2.87) 32(-6,2.87) 33(-5,-2.87) 34(-5,2.87) 35(-4.5,-2.87) 36(-4.5,2.87) 37(-3.5,-2.87) 38(-3.5,2.87) 39(-3,-2.87) 40(-3,2.87) 41(3,-2.87) 42(3,2.87) 43(3.5,-2.87) 44(3.5,2.87) 45(4.5,-2.87) 46(4.5,2.87) 47(5,-2.87) 48(5,2.87) 49(6,-2.87) 50(6,2.87) 51(6.5,-2.87) 52(6.5,2.87) 53(7.5,-2.87) 54(7.5,2.87) 55(8,-2.87) 56(8,2.87) 57(9,-2.87) 58(9,2.87) 59(9.5,-2.87) 60(9.5,2.87) 61(10.5,-2.87) 62(10.5,2.87) 63(11,-2.87) 64(11,2.87) 65(12,-2.87) 66(12,2.87) 67(12.5,-2.87) 68(12.5,2.87) 69(13.5,-2.87) 70(13.5,2.87) 71(14,-2.87) 72(14,2.87) 73(15,-2.87) 74(15,2.87) 75(15.5,-2.87) 76(15.5,2.87) 77(16.5,-2.87) 78(16.5,2.87) 79(17,-2.87) 80(17,2.87)
  rect 2.54x0.43 smd: 81(-17.81,0) 84(-1.69,0) 85(2.19,0) 88(18.31,0)
  rect 4.7x0.43 smd: 82(-12.93,0) 83(-6.58,0) 86(7.08,0) 87(13.43,0)
  round 1.15 hole 1.15 unplated mask+0.254: MH1(-19.81,2.67) MH2(20.326,2.67)
  silkscreen extent -20.47,-4.17 20.89,3.62, body extent -20.42,-3.74 20.89,3.75, height 3.17
SMA [mm] "Molded Diode, 2-Leads, Body 4.3x2.6mm, IPC Medium Density, based on OnSemi component dimensions and land pattern"
  rect 2x2 smd: 1(-2,0) 2(2,0)
  silkscreen extent -3.66,-1.57 2.79,1.57, body extent -2.6,-1.3 2.6,1.3, height 2.42
SNT-100-BK-G [mil] "Samtec STEP model"
  round 1 on Mech3: 0(0,0)
  body extent -100,-50 100,50, height 344
SOT-23 [mm] "SOT23, 3-Leads, Body 2.9x1.3mm, Pitch 0.95mm, Lead Span 2.5mm, IPC Medium Density"
  rrect50% 1x0.6 smd: 1(-1.2,0.95) 2(-1.2,-0.95) 3(1.2,0)
  silkscreen extent -1.63,-1.5 0.7,1.5, body extent -1.16,-1.45 1.21,1.45, height 1
Sullins_GRPB042VWVN [mm] "Header, 1.27mm, 4x2, TH"
  rect 1.05x1.05 hole 0.7: 1(-0.635,1.905)
  round 1.05 hole 0.7: 2(0.635,1.905) 3(-0.635,0.635) 4(0.635,0.635) 5(-0.635,-0.635) 6(0.635,-0.635) 7(-0.635,-1.905) 8(0.635,-1.905)
  silkscreen extent -2,-2.54 1.7,2.64, body extent -1.7,-2.54 1.7,2.54, height 4
TE_5-146278-2 [mm] "TE CONNECTIVITY"
  rect 1.65x1.65 hole 1: 1(-1.27,0)
  round 1.65 hole 1: 2(1.27,0)
  silkscreen extent -2.92,-1.27 2.54,1.27, body extent -2.41,-1.17 2.41,1.17, height 8.13
TI_Stacked_Overlay_Small [mil]
  silkscreen extent -418,-98 418,98
TSW-103-07-G-D [mm] "Samtec 100mil, 2x3, 230 mil above insulator"
  rect 1.65x1.65 hole 1.016: 1(-2.54,-1.27)
  round 1.65 hole 1.016: 2(-2.54,1.27) 3(0,-1.27) 4(0,1.27) 5(2.54,-1.27) 6(2.54,1.27)
  silkscreen extent -4.83,-2.54 3.81,2.54, body extent -3.81,-2.54 3.81,2.54, height 8.38
WL-SMCW_RED [mm] "WURTH"
  rect 0.8x0.8 smd: 1(-0.8,0) 2(0.8,0)
  silkscreen extent -1.9,-0.8 1.2,0.8, body extent -0.85,-0.45 0.85,0.45, height 0.8

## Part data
BA1 BA2 BA3 BA4: "Banana Jack Connector Standard Banana Threaded, External (Nut), TH", Current_A=36, Manufacturer="BK Precision", Supplier Part Number 1=BKCT2220-ND
C1 C2 C4 C9 C10 C22 C23 C24 C31 C32 C33 C42: "CAP, CERM, 10 µF, 25 V, +/- 10%, X7R, 0805", Cap_Case=0805, Manufacturer=MuRata, Supplier Part Number 1=81-GRM21BZ71E106KE5L, TempCo=X7R, Tolerance_%=10, Value1=Unknown, Value2=25V, ValueDisplayed=10µF
C3 C8 C13 C14 C20 C29 C34 C36 C37 C38 C39 C41 C43 C44 C45 C46 C47 C48 C49 C51 C52: "CAP, CERM, 0.1 µF, 16 V, +/- 10%, X7R, 0402", Cap_Case=0402, Manufacturer=MuRata, Supplier Part Number 1=490-3261-1-ND, TempCo=X7R, Tolerance_%=10, Value1=Unknown, Value2=16V, ValueDisplayed=0.1µF
C5 C17 C25 C40: "CAP, CERM, 0.1 µF, 25 V, +/- 10%, X7R, 0402", Cap_Case=0402, Manufacturer=MuRata, Supplier Part Number 1=490-10698-1-ND, TempCo=X7R, Tolerance_%=10, Value1=Unknown, Value2=25V, ValueDisplayed=0.1µF
C6 C11: "CAP, CERM, 22 µF, 10 V, +/- 10%, X7R, 1206", Cap_Case=1206, Manufacturer="Taiyo Yuden", Supplier Part Number 1=587-3425-1-ND, TempCo=X7R, Tolerance_%=10, Value1=Unknown, Value2=10V, ValueDisplayed=22µF
C7 C28 C55: "CAP, TA, 10 µF, 16 V, +/- 10%, 0.45 ohm, SMD", Cap_Case=C, Manufacturer=Vishay-Sprague, Supplier Part Number 1=718-1097-1-ND, Tolerance_%=10, Value1="0.45 ohm", Value2=16V, ValueDisplayed=10µF
C12 C21: "CAP, CERM, 4.7 µF, 16 V, +/- 20%, X5R, 0402", Cap_Case=0402, Manufacturer=MuRata, TempCo=X5R, Tolerance_%=20, Value1=Unknown, Value2=16V, ValueDisplayed=4.7µF
C15: "CAP, CERM, 13 pF, 50 V, +/- 5%, C0G/NP0, 0402", Cap_Case=0402, Manufacturer=MuRata, Supplier Part Number 1=81-GRM1555C1H130JA1D, TempCo=C0G/NP0, Tolerance_%=5, Value1=Unknown, Value2=50V, ValueDisplayed=13pF
C16: "CAP, CERM, 1 µF, 25 V, +/- 10%, X5R, 0402", Cap_Case=0402, Manufacturer=MuRata, Supplier Part Number 1=490-10017-1-ND, TempCo=X5R, Tolerance_%=10, Value1=Unknown, Value2=25V, ValueDisplayed=1µF
C18 C19: "CAP, CERM, 4.7 pF, 25 V, +/- 5%, C0G/NP0, 0402", Cap_Case=0402, Manufacturer=MuRata, Supplier Part Number 1=81-GRM1555C1E4R7CA1D, TempCo=C0G/NP0, Tolerance_%=5, Value1=Unknown, Value2=25V, ValueDisplayed=4.7pF
C26 C27: "CAP, CERM, 33 pF, 25 V,+/- 5%, C0G/NP0, 0402", Cap_Case=0402, Manufacturer="Wurth Elektronik", Supplier Part Number 1=710-885012005043, TempCo=C0G/NP0, Tolerance_%=5, Value2=25V, ValueDisplayed=33pF
C35: "CAP, CERM, 56 pF, 50 V, +/- 5%, C0G/NP0, 0402", Cap_Case=0402, Manufacturer=MuRata, Supplier Part Number 1=81-GRM1555C1H560JA1D, TempCo=C0G/NP0, Tolerance_%=5, Value1=Unknown, Value2=50V, ValueDisplayed=56pF
C50 C53 C54: "CAP, CERM, 100 pF, 50 V, +/- 10%, X7R, 0402", Cap_Case=0402, Manufacturer="Yageo America", Supplier Part Number 1=311-1419-1-ND, TempCo=X7R, Tolerance_%=10, Value1=Unknown, Value2=50V, ValueDisplayed=100pF
D1 D2: "LED, Red, SMD", Color=Red, Manufacturer="Wurth Elektronik", Power_TotalModule=0.072, Supplier Part Number 1=732-4978-1-ND, Value1=0.072W, Value2=2V
DA1 DA3: "Diode, Schottky, 40 V, 1 A, AEC-Q101, SMA", Manufacturer=Vishay-Semiconductor, Supplier Part Number 1=SS14HE3_A/H-ND, Value1=1A, Value2=0.5V
DA2: "Diode, Schottky, 30 V, 0.1 A, SOT-23", Manufacturer=Panasonic, Supplier Part Number 1=DB3X316F0LCT-ND, Value1=0.1A, Value2=0.55V
FID1 FID2 FID3: "Fiducial mark.  There is nothing to buy or mount.", Manufacturer=N/A
H1 H2 H3 H4: "Machine Screw, Round, #4-40 x 1/4, Nylon, Philips panhead", DigiKeyPartNumber=H542-ND, Manufacturer="B&F Fastener Supply"
H5 H6 H7 H8: "Standoff, Hex, 0.5\"L #4-40 Nylon", Alternate Manufacturer=-, Manufacturer=Keystone, Supplier Part Number 1=1902CK-ND
J1 J3: "Header, 100mil, 2x1, Tin, TH", Manufacturer="TE Connectivity", Supplier Part Number 1=5-146278-2-ND
J2 J4 J5: "Header, 1.27mm, 4x2, TH", Color=Black, Manufacturer="Sullins Connector Solutions", Supplier Part Number 1=S9015E-04-ND
J6: "Header, 100mil, 3x2, Gold, TH", Color=Black, Current_A=6.3, Manufacturer=Samtec, Supplier Part Number 1=SAM1028-03-ND, Voltage_V=550
J7: "Socket, 40x2, Gold, SMD", Manufacturer=Samtec, Supplier Part Number 1=88K0281
L1 L3 L6 L7 L10: "Ferrite Bead, 1500 ohm @ 100 MHz, 1 A, 0805", Manufacturer="Wurth Elektronik", Supplier Part Number 1=732-4649-1-ND, Value1="0.3 ohm", Value2=1A, ValueDisplayed="1500 ohm"
L2 L4 L5 L11: "Ferrite Bead, 600 ohm @ 100 MHz, 0.2 A, 0402", Manufacturer=TDK, Supplier Part Number 1=445-172776-1-ND, Value1="0.85 ohm", Value2=0.2A, ValueDisplayed="600 ohm"
LBL1: library part THT-14-423-10, "Thermal Transfer Printable Labels, 0.650\" W x 0.200\" H - 10,000 per roll", Alternate Manufacturer=-, Manufacturer=Brady, Supplier Part Number 1=2065596
Logo1: library part TI_Logo, "Texas Instrument Corporate Signature"
Logo2: library part Pb-Free
Logo3: library part FCC_disclaimer, "FCC_disclaimer"
R1 R17 R32: "RES, 50, 1%, 0.1 W, 0603", Manufacturer=Vishay-Dale, Power_W=0.1, Supplier Part Number 1=71-CRCW0603-50-E3, TempCo="100 ppm/C", Tolerance_%=1, Value1=1%, Value2=0.1W, Value_Code=50R0, ValueDisplayed=50
R2 R3: "RES, 2.49 k, 1%, 0.063 W, 0402", Manufacturer=Vishay-Dale, Power_W=0.063, Supplier Part Number 1=541-2.49KLCT-ND, TempCo="100 ppm/C", Tolerance_%=1, Value1=1%, Value2=0.063W, Value_Code=2k49, ValueDisplayed=2.49k
R4 R9: "RES, 10.0, 1%, 0.063 W, 0402", Manufacturer=Vishay-Dale, Power_W=0.063, Supplier Part Number 1=541-10.0LCT-ND, TempCo="100 ppm/C", Tolerance_%=1, Value1=1%, Value2=0.063W, Value_Code=10R0, ValueDisplayed=10.0
R5 R19 R21 R22 R25 R27: "RES, 0, 5%, 0.063 W, 0402", Manufacturer=Panasonic, Power_W=0.063, Supplier Part Number 1=P0.0JCT-ND, TempCo="600 ppm/C", Tolerance_%=5, Value1=5%, Value2=0.063W, Value_Code=0000, ValueDisplayed=0
R6 R23: "RES, 1.0 k, 5%, 0.063 W, 0402", Manufacturer=Vishay-Dale, Power_W=0.063, Supplier Part Number 1=541-1.0KJCT-ND, TempCo="200 ppm/C", Tolerance_%=5, Value1=5%, Value2=0.063W, Value_Code=1k00, ValueDisplayed=1.0k
R7 R8 R10 R11: "RES, 1.00 k, 0.1%, 0.063 W, 0402", Manufacturer=Panasonic, Power_W=0.063, Supplier Part Number 1=P1.0KDCCT-ND, TempCo="25 ppm/C", Tolerance_%=0.1, Value1=0.1%, Value2=0.063W, Value_Code=1k00, ValueDisplayed=1.00k
R12 R13: "RES, 130, 1%, 0.063 W, 0402", Manufacturer=Vishay-Dale, Power_W=0.063, Supplier Part Number 1=541-130LCT-ND, TempCo="100 ppm/C", Tolerance_%=1, Value1=1%, Value2=0.063W, Value_Code=130R, ValueDisplayed=130
R14 R16: "RES, 3.0 k, 5%, 0.063 W, 0402", Manufacturer=Vishay-Dale, Power_W=0.063, Supplier Part Number 1=541-3.0KJCT-ND, TempCo="200 ppm/C", Tolerance_%=5, Value1=5%, Value2=0.063W, Value_Code=3k00, ValueDisplayed=3.0k
R15: "RES, 2.0 k, 5%, 0.063 W, 0402", Manufacturer=Vishay-Dale, Power_W=0.063, Supplier Part Number 1=541-2.0KJCT-ND, TempCo="200 ppm/C", Tolerance_%=5, Value1=5%, Value2=0.063W, Value_Code=2k00, ValueDisplayed=2.0k
R18: "RES, 10.0 k, 0.1%, 0.063 W, 0402", Manufacturer=Rohm, Power_W=0.063, Supplier Part Number 1=RHM10.0KCDCT-ND, TempCo="100 ppm/C", Tolerance_%=0.1, Value1=0.1%, Value2=0.063W, Value_Code=10k0, ValueDisplayed=10.0k
R20 R24 R26: "RES, 100, 1%, 0.063 W, 0402", Manufacturer=Vishay-Dale, Power_W=0.063, Supplier Part Number 1=541-100LCT-ND, TempCo="100 ppm/C", Tolerance_%=1, Value1=1%, Value2=0.063W, Value_Code=100R, ValueDisplayed=100
R28 R29: "RES, 10 k, 5%, 0.063 W, 0402", Manufacturer=Vishay-Dale, Power_W=0.063, Supplier Part Number 1=541-10KJCT-ND, TempCo="200 ppm/C", Tolerance_%=5, Value1=5%, Value2=0.063W, Value_Code=10k0, ValueDisplayed=10k
R30 R33 R35: "RES, 10.0 k, 1%, 0.063 W, 0402", Manufacturer=Vishay-Dale, Power_W=0.063, Supplier Part Number 1=541-10.0KLCT-ND, TempCo="100 ppm/C", Tolerance_%=1, Value1=1%, Value2=0.063W, Value_Code=10k0, ValueDisplayed=10.0k
R31 R34 R36: "RES, 1.00 k, 1%, 0.063 W, 0402", Manufacturer=Vishay-Dale, Power_W=0.063, Supplier Part Number 1=541-1.00KLCT-ND, TempCo="100 ppm/C", Tolerance_%=1, Value1=1%, Value2=0.063W, Value_Code=1k00, ValueDisplayed=1.00k
R37 R38: "RES, 22, 5%, 0.0625 W, Resistor Array - 8x1", Manufacturer=Panasonic, Power_W=0.0625, Supplier Part Number 1=Y1220CT-ND, TempCo="200 ppm/C", Tolerance_%=5, Value1=5%, Value2=0.0625W, Value_Code=22R0, ValueDisplayed=22
S1 S2 S3 S4: "SMA JACK 50 OHM EDGE MNT, SMT", Color=Gold, Manufacturer=Johnson, Supplier Part Number 1=J629-ND
SH-J1 SH-J2: "Shunt, 100mil, Gold plated, Black", Alternate Manufacturer=Samtec, Alternate PartNumber=SNT-100-BK-G, Manufacturer=3M, Supplier Part Number 1=3M9580-ND
T1: "RF Transformer, 75 ohm, 0.4 to 800 MHz, SMT", Manufacturer=Minicircuits
TP1 TP2 TP4 TP5 TP7: "Test Point, Miniature, Orange, TH", Color=Orange, Manufacturer=Keystone, Supplier Part Number 1=36-5003-ND
TP3 TP6: "Test Point, Miniature, Black, TH", Color=Black, Manufacturer=Keystone, Supplier Part Number 1=36-5001-ND
U1: "Single Output High PSRR LDO, 150 mA, Fixed 5 V Output, 2.5 to 6.5 V Input, with Low IQ, 6-pin WSON (DSE), -40 to 125 degC, Green (RoHS & no Sb/Br)", Alternate Manufacturer="Texas Instruments", Alternate PartNumber=Equivalent, Supplier Part Number 1=296-25447-2-ND
U2: "High-Speed, High-Precision, Low-Distortion 16-Bit and 18-Bit Analog-to-Digital Converter (ADC) Drivers, DGK0008A (VSSOP-8)", Alternate Manufacturer="Texas Instruments", Alternate PartNumber=OPA2626IDGKT
U3: "Low Power, Precision, 160MHz, Fully Differential Amplifier, RUN0010A", Alternate Manufacturer="Texas Instruments", Alternate PartNumber=THS4551IRUNT
U4: "Single Output High PSRR LDO, 150 mA, Fixed 1.8 V Output, 2.5 to 6.5 V Input, with Low IQ, 6-pin WSON (DSE), -40 to 125 degC, Green (RoHS & no Sb/Br)", Alternate Manufacturer="Texas Instruments", Alternate PartNumber=Equivalent, Supplier Part Number 1=TPS71718DSET-ND
U5: "14-Bit, 65-MSPS, Ultra Low-Power ADC, RGZ0048D (VQFN-48)", Alternate Manufacturer="Texas Instruments", Alternate PartNumber=ADS4142IRGZT
ZZ1: library part AssemblyNoteLabel, Alternate Manufacturer=-
ZZ2 ZZ3 ZZ4: library part AssemblyNote, Alternate Manufacturer=-

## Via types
v1: diameter 12, hole 6, Top Layer to Bottom Layer, 153 vias
v2: diameter 40, hole 20, Top Layer to Bottom Layer, 35 vias
v3: diameter 19.68, hole 7.87, Top Layer to Bottom Layer, 21 vias
v4: diameter 32, hole 16, Top Layer to Bottom Layer, 10 vias
v5: diameter 16, hole 8, Top Layer to Bottom Layer, 4 vias
v6: diameter 56, hole 28, Top Layer to Bottom Layer, 2 vias
v7: diameter 60, hole 30, Top Layer to Bottom Layer, 2 vias
v8: diameter 20, hole 10, Top Layer to Bottom Layer, 2 vias

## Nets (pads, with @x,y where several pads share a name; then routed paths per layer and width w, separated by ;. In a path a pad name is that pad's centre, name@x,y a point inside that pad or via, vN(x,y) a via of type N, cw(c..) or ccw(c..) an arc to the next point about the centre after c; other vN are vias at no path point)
+1V8_OUT: C23.1 J3.1 TP5.1 U4.1 | length 353.6
  Top Layer w10: 1578.68,869.68 U4.1@1625.59,869.68
  Top Layer w50: C23.1@1525,893.29 J3.1@1525,1025 TP5.1@1700,1025
+1V8A: C24.1 C29.1 J4.1 L6.2 L11.1 R14.2 TP4.1 | length 984.7
  Top Layer w15: v1(2005,1800) L11.1@2005,1825 v1(2005,1850)
  PWR w10: v1(1650,2305) 1675,2280 1675,1875 1750,1800 v1(2005,1800)
  PWR w12: J4.1@1525,2325 1629.99,2325.01 v1(1650,2305)
  other v1: 1700,1270 2004.79,1824.79
  other v2: 1525,1290 1625,1290 1625,1362 1697,1362 1659,1434
+5V0_OUT: C2.1 J1.1 TP2.1 U1.1 | length 419
  Top Layer w10: C2.1@425,890 477,890 497.32,869.68 U1.1@525.59,869.68
  Top Layer w50: C2.1@425,890 J1.1@425,1025 TP2.1@600,1025
+5V0A: C4.1 C8.1 L1.2 L4.1 L5.1 R3.2 TP1.1
  other v1: 600,1275 830,1860 1343.24,2018 430,2140
  other v2: 425,1290 525,1290 525,1362 597,1362 559,1434
\ADC_SEN: C50.1 R31.1 U5.27 | length 588.6
  Top Layer w6: U5.27@2181.1,1891.14 2181.1,1865.99 2187.09,1860 2187.09,1694.91 2331,1551 2331,1406 C50.1@2330,1405 R31.1@2370,1405
\SEN_IN: J6.2 R30.1 R31.2 | length 1334.5
  Top Layer w6: R31.2@2370,1365 R30.1@2370,1330 2370,1271.3 2436.3,1205 2436.3,794.33 2900,330.63 J6.2@2900,250
ACLKOUT_N: R38.2 U5.4 | length 471
  Top Layer w6: U5.4@2299.21,2158.86 2299.21,2173.67 2296.37,2176.51 2296.37,2236.37 2320,2260 2395.2,2260 2471.42,2183.78 2628.07,2183.78 2632.63,2179.21 R38.2@2645.47,2179.21
ACLKOUT_P: R38.1 U5.5 | length 494.2
  Top Layer w6: U5.5@2279.53,2158.86 2279.53,2173.67 2282.37,2176.51 2282.37,2242.17 2310.2,2270 2314.2,2274 2401,2274 2477.22,2197.78 2628.07,2197.78 2632.63,2202.34 R38.1@2645.47,2202.34
AD0_AD1_N: R37.8 U5.33 | length 502.1
  Top Layer w6: U5.33@2299.21,1891.14 2299.21,1876.33 2302.06,1873.49 2302.06,1865 2290,1852.94 2290,1795.2 2300.1,1785.1 2314.2,1771 2395.8,1771 2405.8,1781 2475.8,1851 2629.29,1851 2632.63,1847.66 R37.8@2645.47,1847.66
AD0_AD1_P: R37.7 U5.34 | length 479.9
  Top Layer w6: U5.34@2318.9,1891.14 2318.9,1876.33 2316.06,1873.49 2316.06,1859.2 2304,1847.15 2304,1801 2320,1785 2390,1785 2470,1865 2626.84,1865 2632.63,1870.79 R37.7@2645.47,1870.79
AD2_AD3_N: R37.6 U5.37 | length 274.8
  Top Layer w6: U5.37@2383.86,1916.73 2398.67,1916.73 2401.51,1919.57 2445.63,1919.57 2471.89,1893.32 2629.79,1893.32 2632.63,1890.47 R37.6@2645.47,1890.47
AD2_AD3_P: R37.5 U5.38 | length 274.8
  Top Layer w6: U5.38@2383.86,1936.42 2398.67,1936.42 2401.51,1933.57 2451.43,1933.57 2477.68,1907.32 2629.79,1907.32 2632.63,1910.16 R37.5@2645.47,1910.16
AD4_AD5_N: R37.4 U5.39 | length 274.8
  Top Layer w6: U5.39@2383.86,1956.1 2398.67,1956.1 2401.51,1958.94 2456.26,1958.94 2482.52,1932.68 2629.79,1932.68 2632.63,1929.84 R37.4@2645.47,1929.84
AD4_AD5_P: R37.3 U5.40 | length 274.8
  Top Layer w6: U5.40@2383.86,1975.79 2398.67,1975.79 2401.51,1972.94 2462.06,1972.94 2488.32,1946.68 2629.79,1946.68 2632.63,1949.53 R37.3@2645.47,1949.53
AD6_AD7_N: R37.2 U5.41 | length 274.8
  Top Layer w6: U5.41@2383.86,1995.47 2398.67,1995.47 2401.51,1998.32 2466.89,1998.32 2490.81,1974.39 2627.45,1974.39 2632.63,1969.21 R37.2@2645.47,1969.21
AD6_AD7_P: R37.1 U5.42 | length 274.3
  Top Layer w6: U5.42@2383.86,2015.16 2398.67,2015.16 2401.51,2012.32 2472.68,2012.32 2496.61,1988.39 2628.68,1988.39 2632.63,1992.34 R37.1@2645.47,1992.34
AD8_AD9_N: R38.8 U5.43 | length 274.8
  Top Layer w6: U5.43@2383.86,2034.84 2398.67,2034.84 2401.51,2037.69 2470.46,2037.69 2495,2062.22 2628.07,2062.22 2632.63,2057.66 R38.8@2645.47,2057.66
AD8_AD9_P: R38.7 U5.44 | length 274.8
  Top Layer w6: U5.44@2383.86,2054.53 2398.67,2054.53 2401.51,2051.69 2464.66,2051.69 2489.2,2076.22 2628.07,2076.22 2632.63,2080.79 R38.7@2645.47,2080.79
AD10_AD11_N: R38.6 U5.45 | length 274.8
  Top Layer w6: U5.45@2383.86,2074.21 2398.67,2074.21 2401.51,2077.06 2457.06,2077.06 2483.32,2103.32 2629.79,2103.32 2632.63,2100.47 R38.6@2645.47,2100.47
AD10_AD11_P: R38.5 U5.46 | length 274.8
  Top Layer w6: U5.46@2383.86,2093.9 2398.67,2093.9 2401.51,2091.06 2451.26,2091.06 2477.52,2117.32 2629.79,2117.32 2632.63,2120.16 R38.5@2645.47,2120.16
AD12_AD13_N: R38.4 U5.47 | length 274.8
  Top Layer w6: U5.47@2383.86,2113.58 2398.67,2113.58 2401.51,2116.43 2446.43,2116.43 2472.68,2142.68 2629.79,2142.68 2632.63,2139.84 R38.4@2645.47,2139.84
AD12_AD13_P: R38.3 U5.48 | length 274.8
  Top Layer w6: U5.48@2383.86,2133.27 2398.67,2133.27 2401.51,2130.43 2440.63,2130.43 2466.89,2156.68 2629.79,2156.68 2632.63,2159.53 R38.3@2645.47,2159.53
ADC_AVDD: C36.1 C37.1 C38.1 C39.1 C46.1 C48.1 L11.2 U5.8 U5.18 U5.20 U5.22 U5.24 U5.26 | length 869.1
  Top Layer w10: C39.1@2044.58,2034.58 v1(2045,2035) U5.18@2115.98,2035 ; v1(2045,1825) L11.2@2045.42,1825.42 ; v1(2045,1915) C36.1@2046.52,1916.52 ; v1(2045,1955) C37.1@2045.42,1955.42 ; v1(2045,1995) C38.1@2045.42,1995.42 ; C38.1@2045.47,1995.47 U5.20@2116.14,1995.47 ; C37.1@2046.1,1956.1 U5.22@2116.14,1956.1 ; C36.1@2046.73,1916.73 U5.24@2116.14,1916.73 ; v1(2161,1825) 2161.42,1825.42 U5.26@2161.42,1891.14 ; U5.8@2220.47,2158.86 2220.47,2195.47 2230,2205 v1(2230,2225)
  Top Layer w15: v1(2045,1800) v1(2045,1825) v1(2045,1850)
  PWR w10: v1(2045,1995) 2045.47,1995.47 2199.83,1995.47 2220.47,2016.11 2220.47,2215.47 v1(2230,2225)
ADC_DFS: J4.2 J4.4 J4.6 J4.8 U5.6 | length 1038.5
  Top Layer w6: v1(2259.84,2158.86) U5.6@2260.87,2159.89
  Bottom Layer w8: J4.8@1475,2475 J4.6@1475,2425 J4.4@1475,2375 J4.2@1475,2325 1475,2268 1514,2229 2052,2229 2093,2188 2230.7,2188 v1(2259.84,2158.86)
ADC_DVDD: C42.1 C47.1 C51.1 C52.1 L10.2 R28.2 R30.2 R33.2 R35.2 TP7.1 U5.2 U5.35 | length 321.4
  Top Layer w10: v1(2328,1825) 2338.58,1835.58 U5.35@2338.58,1891.14 ; v1(2328,2225) 2338.58,2214.42 U5.2@2338.58,2158.86
  PWR w10: v1(2190,2275) 2315,2275 2328,2262 v1(2328,2225)
  other v1: 2175,1270 2330,1330 2410,1330 2490,1330
  other v2: 2000,1290 2100,1290 2100,1362 2172,1362 2134,1434
ADC_OVR: J7.6 U5.3 | length 1500.1
  Bottom Layer w8: v1(2318.9,2158.86) 2350.04,2190 2398.74,2190 2588.74,2380 3560,2380 3594.76,2345.24 v1(3712.99,2345.24)
ADC_SCLK: C54.1 R36.1 U5.29 | length 642.7
  Top Layer w6: U5.29@2220.47,1891.14 2220,1890.67 2220,1865.51 2214.49,1860 2214.49,1711.51 2490,1436 C54.1@2490,1405 R36.1@2530,1405
ADC_SDI: C53.1 R34.1 U5.28 | length 612.8
  Top Layer w6: U5.28@2200.79,1891.14 2200.79,1705.21 2410,1496 C53.1@2410,1405 R34.1@2450,1405
ADC_VCM: C40.1 R9.2 U5.13 | length 1144.6
  Top Layer w8: v1(2045,2160) 2065,2160 2091.73,2133.27 U5.13@2116.14,2133.27
  Bottom Layer w8: v1(1245,1835.81) 1350,1940.81 1500.81,1940.81 1570,2010 1570,2153.3 1630,2213.3 1991.7,2213.3 v1(2045,2160)
ADCIN_N: R21.2 U5.16 | length 83.5
  Top Layer w8: R21.2@2045,2080 2057,2092 2073,2092 2090.79,2074.21 U5.16@2116.14,2074.21
ADCIN_P: R22.2 U5.15 | length 82
  Top Layer w8: R22.2@2045,2120 2057,2108 2079.63,2108 2083.13,2104.5 2093.73,2093.9 U5.15@2116.14,2093.9
CLK_N: C43.1 R24.1 U5.11 | length 214.8
  Top Layer w8: C43.1@2080,2330 2092,2318 2092,2287 R24.1@2080,2275 2092,2263 2092,2244.09 2161.42,2174.67 U5.11@2161.42,2158.86
CLK_P: C45.1 R24.2 U5.10 | length 216.3
  Top Layer w8: C45.1@2120,2330 2108,2318 2108,2287 R24.2@2120,2275 2108,2263 2108,2250.72 2181.1,2177.61 U5.10@2181.1,2158.86
CLKOUT_N: J7.3 R38.15 | length 869.9
  Top Layer w6: R38.15@2704.53,2179.21 2717.37,2179.21 2721.94,2183.78 2868.78,2183.78 3072.45,2387.45 3436.48,2387.45 3439.32,2384.61 J7.3@3487.01,2384.61
CLKOUT_P: J7.1 R38.16 | length 869.9
  Top Layer w6: R38.16@2704.53,2202.34 2717.37,2202.34 2721.93,2197.78 2862.98,2197.78 3066.65,2401.45 3436.48,2401.45 3439.32,2404.29 J7.1@3487.01,2404.29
